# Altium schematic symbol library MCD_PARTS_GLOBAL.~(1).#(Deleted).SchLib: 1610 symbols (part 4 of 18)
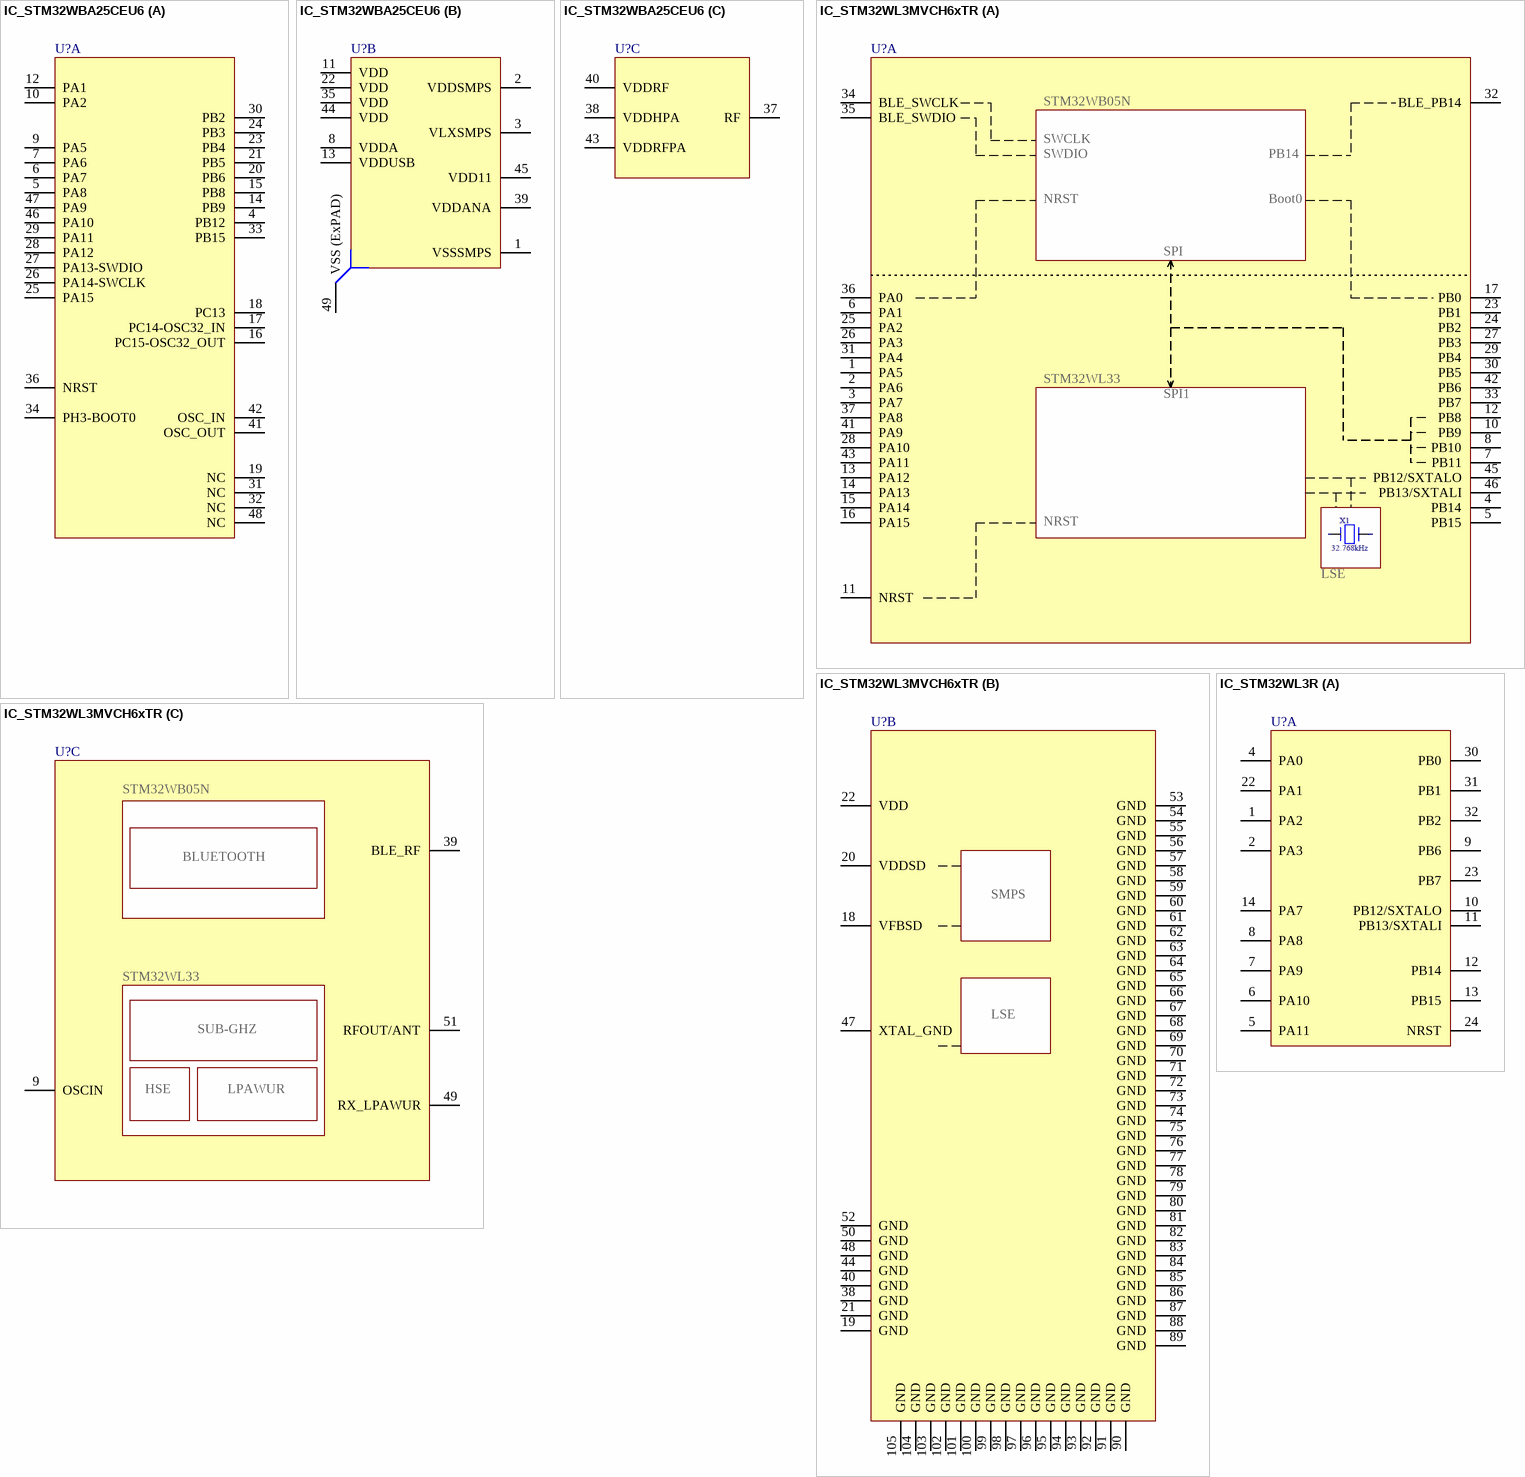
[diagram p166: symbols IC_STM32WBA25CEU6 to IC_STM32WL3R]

## IC_STM32WL3MVCH6xTR
designator U?
part A pins: 1 PA5, 2 PA6, 3 PA7, 4 PB14, 5 PB15, 6 PA1, 7 PB11, 8 PB10, 10 PB9, 11 NRST, 12 PB8, 13 PA12, 14 PA13, 15 PA14, 16 PA15, 17 PB0, 23 PB1, 24 PB2, 25 PA2, 26 PA3, 27 PB3, 28 PA10, 29 PB4, 30 PB5, 31 PA4, 32 BLE_PB14, 33 PB7, 34 BLE_SWCLK, 35 BLE_SWDIO, 36 PA0, 37 PA8, 41 PA9, 42 PB6, 43 PA11, 45 PB12/SXTALO, 46 PB13/SXTALI
part B pins: 18 VFBSD, 19 GND, 20 VDDSD, 21 GND, 22 VDD, 38 GND, 40 GND, 44 GND, 47 XTAL_GND, 48 GND, 50 GND, 52 GND, 53 GND, 54 GND, 55 GND, 56 GND, 57 GND, 58 GND, 59 GND, 60 GND, 61 GND, 62 GND, 63 GND, 64 GND, 65 GND, 66 GND, 67 GND, 68 GND, 69 GND, 70 GND, 71 GND, 72 GND, 73 GND, 74 GND, 75 GND, 76 GND, 77 GND, 78 GND, 79 GND, 80 GND, 81 GND, 82 GND, 83 GND, 84 GND, 85 GND, 86 GND, 87 GND, 88 GND, 89 GND, 90 GND, 91 GND, 92 GND, 93 GND, 94 GND, 95 GND, 96 GND, 97 GND, 98 GND, 99 GND, 100 GND, 101 GND, 102 GND, 103 GND, 104 GND, 105 GND
part C pins: 9 OSCIN, 39 BLE_RF, 49 RX_LPAWUR, 51 RFOUT/ANT

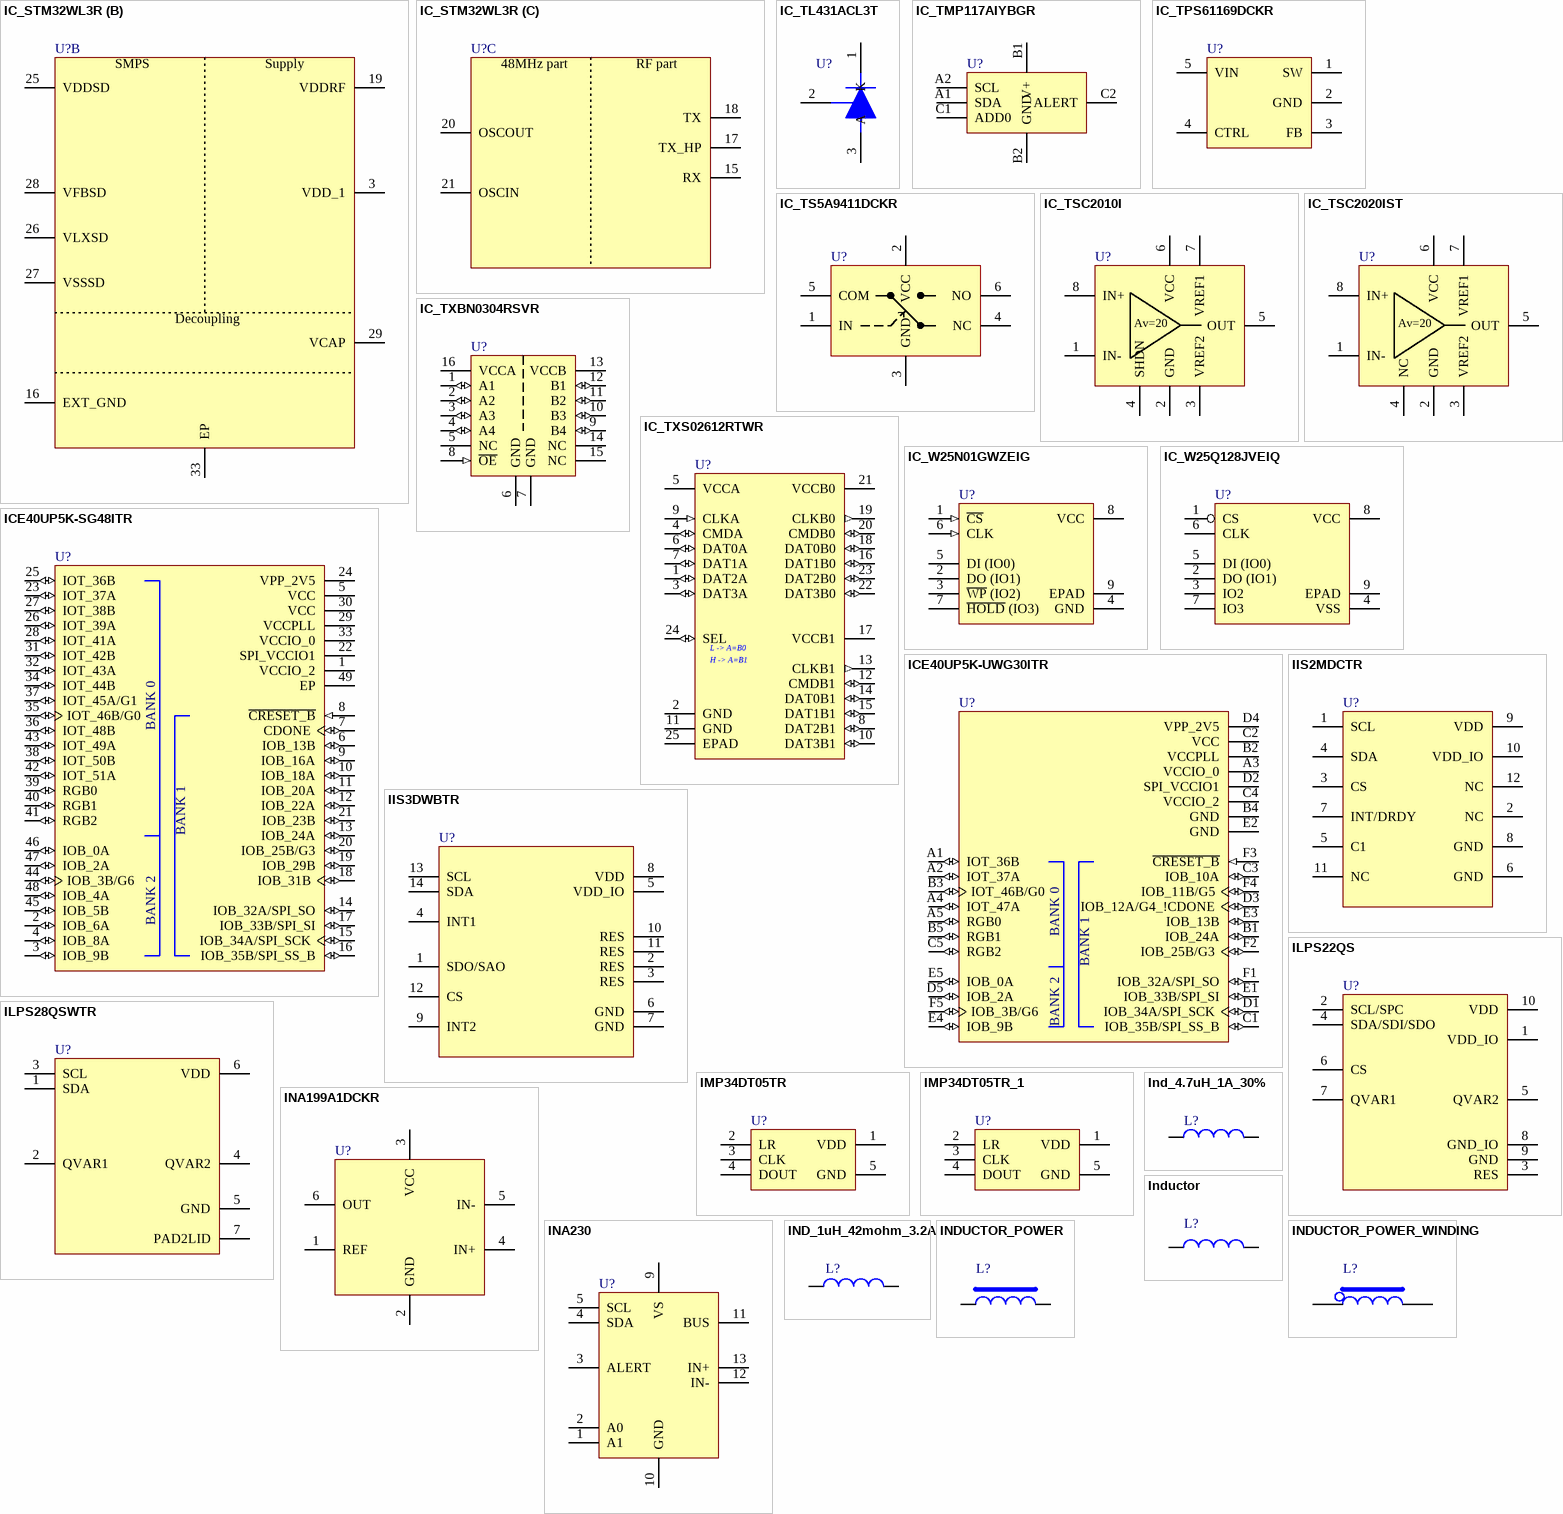
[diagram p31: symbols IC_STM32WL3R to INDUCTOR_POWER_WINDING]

## IC_STM32WL3R
designator U?
part A pins: 1 PA2, 2 PA3, 4 PA0, 5 PA11, 6 PA10, 7 PA9, 8 PA8, 9 PB6, 10 PB12/SXTALO, 11 PB13/SXTALI, 12 PB14, 13 PB15, 14 PA7, 22 PA1, 23 PB7, 24 NRST, 30 PB0, 31 PB1, 32 PB2
part B pins: 3 VDD_1, 16 EXT_GND, 19 VDDRF, 25 VDDSD, 26 VLXSD, 27 VSSSD, 28 VFBSD, 29 VCAP, 33 EP
part C pins: 15 RX, 17 TX_HP, 18 TX, 20 OSCOUT, 21 OSCIN

## IC_TL431ACL3T
designator U?
pins: 1 K, 2 Ref, 3 A

## IC_TMP117AIYBGR
designator U?
pins: A1 SDA, A2 SCL, B1 V+, B2 GND, C1 ADD0, C2 ALERT (oc)

## IC_TPS61169DCKR
designator U?
pins: 1 SW, 2 GND, 3 FB, 4 CTRL, 5 VIN

## IC_TS5A9411DCKR
designator U?
pins: 1 IN, 2 VCC, 3 GND, 4 NC, 5 COM, 6 NO

## IC_TSC2010I
designator U?
An Alternate mode is available
pins: 1 IN-, 2 GND, 3 VREF2, 4 SHDN, 5 OUT, 6 VCC, 7 VREF1, 8 IN+
1 alternate drawing of the same symbol

## IC_TSC2020IST
designator U?
pins: 1 IN-, 2 GND, 3 VREF2, 4 NC, 5 OUT, 6 VCC, 7 VREF1, 8 IN+

## IC_TXBN0304RSVR
designator U?
pins: 1 A1 (io), 2 A2 (io), 3 A3 (io), 4 A4 (io), 5 NC, 6 GND (power), 7 GND (power), 8 ~{OE} (in), 9 B4 (io), 10 B3 (io), 11 B2 (io), 12 B1 (io), 13 VCCB (power), 14 NC, 15 NC, 16 VCCA (power)

## IC_TXS02612RTWR
designator U?
pins: 1 DAT2A (io), 2 GND (power), 3 DAT3A (io), 4 CMDA (io), 5 VCCA (power), 6 DAT0A (io), 7 DAT1A (io), 8 DAT2B1 (io), 9 CLKA (in), 10 DAT3B1 (io), 11 GND (power), 12 CMDB1 (io), 13 CLKB1 (out), 14 DAT0B1 (io), 15 DAT1B1 (io), 16 DAT1B0 (io), 17 VCCB1 (power), 18 DAT0B0 (io), 19 CLKB0 (out), 20 CMDB0 (io), 21 VCCB0 (power), 22 DAT3B0 (io), 23 DAT2B0 (io), 24 SEL (io), 25 EPAD

## IC_W25N01GWZEIG
designator U?
pins: 1 ~{CS} (in), 2 DO (IO1), 3 ~{WP} (IO2), 4 GND, 5 DI (IO0), 6 CLK (in), 7 ~{HOLD} (IO3), 8 VCC, 9 EPAD

## IC_W25Q128JVEIQ
designator U?
pins: 1 CS, 2 DO (IO1), 3 IO2, 4 VSS, 5 DI (IO0), 6 CLK, 7 IO3, 8 VCC, 9 EPAD

## ICE40UP5K-SG48ITR
designator U?
pins: 1 VCCIO_2, 2 IOB_6A (io), 3 IOB_9B (io), 4 IOB_8A (io), 5 VCC, 6 IOB_13B (io), 7 CDONE (io), 8 ~{CRESET_B} (in), 9 IOB_16A (io), 10 IOB_18A (io), 11 IOB_20A (io), 12 IOB_22A (io), 13 IOB_24A (io), 14 IOB_32A/SPI_SO (io), 15 IOB_34A/SPI_SCK (io), 16 IOB_35B/SPI_SS_B (io), 17 IOB_33B/SPI_SI (io), 18 IOB_31B (io), 19 IOB_29B (io), 20 IOB_25B/G3 (io), 21 IOB_23B (io), 22 SPI_VCCIO1, 23 IOT_37A (io), 24 VPP_2V5, 25 IOT_36B (io), 26 IOT_39A (io), 27 IOT_38B (io), 28 IOT_41A (io), 29 VCCPLL, 30 VCC, 31 IOT_42B (io), 32 IOT_43A (io), 33 VCCIO_0, 34 IOT_44B (io), 35 IOT_46B/G0 (io), 36 IOT_48B (io), 37 IOT_45A/G1 (io), 38 IOT_50B (io), 39 RGB0 (io), 40 RGB1 (io), 41 RGB2 (io), 42 IOT_51A (io), 43 IOT_49A (io), 44 IOB_3B/G6 (io), 45 IOB_5B (io), 46 IOB_0A (io), 47 IOB_2A (io), 48 IOB_4A (io), 49 EP

## ICE40UP5K-UWG30ITR
designator U?
pins: A1 IOT_36B (io), A2 IOT_37A (io), A3 VCCIO_0, A4 IOT_47A (io), A5 RGB0 (io), B1 IOB_24A (io), B2 VCCPLL, B3 IOT_46B/G0 (io), B4 GND, B5 RGB1 (io), C1 IOB_35B/SPI_SS_B (io), C2 VCC, C3 IOB_10A (io), C4 VCCIO_2, C5 RGB2 (io), D1 IOB_34A/SPI_SCK (io), D2 SPI_VCCIO1, D3 IOB_12A/G4_!CDONE (io), D4 VPP_2V5, D5 IOB_2A (io), E1 IOB_33B/SPI_SI (io), E2 GND, E3 IOB_13B (io), E4 IOB_9B (io), E5 IOB_0A (io), F1 IOB_32A/SPI_SO (io), F2 IOB_25B/G3 (io), F3 ~{CRESET_B} (in), F4 IOB_11B/G5 (io), F5 IOB_3B/G6 (io)

## IIS2MDCTR
designator U?
pins: 1 SCL, 2 NC, 3 CS, 4 SDA, 5 C1, 6 GND, 7 INT/DRDY, 8 GND, 9 VDD, 10 VDD_IO, 11 NC, 12 NC

## IIS3DWBTR
designator U?
pins: 1 SDO/SAO, 2 RES, 3 RES, 4 INT1, 5 VDD_IO, 6 GND, 7 GND, 8 VDD, 9 INT2, 10 RES, 11 RES, 12 CS, 13 SCL, 14 SDA

## ILPS22QS
designator U?
pins: 1 VDD_IO, 2 SCL/SPC, 3 RES, 4 SDA/SDI/SDO, 5 QVAR2, 6 CS, 7 QVAR1, 8 GND_IO, 9 GND, 10 VDD

## ILPS28QSWTR
designator U?
pins: 1 SDA, 2 QVAR1, 3 SCL, 4 QVAR2, 5 GND, 6 VDD, 7 PAD2LID

## IMP34DT05TR
designator U?
pins: 1 VDD, 2 LR, 3 CLK, 4 DOUT, 5 GND

## IMP34DT05TR_1
designator U?
pins: 1 VDD, 2 LR, 3 CLK, 4 DOUT, 5 GND

## INA199A1DCKR
designator U?
pins: 1 REF, 2 GND, 3 VCC, 4 IN+, 5 IN-, 6 OUT

## INA230
designator U?
pins: 1 A1, 2 A0, 3 ALERT, 4 SDA, 5 SCL, 6 NC hidden, 7 NC hidden, 8 NC hidden, 9 VS, 10 GND, 11 BUS, 12 IN-, 13 IN+, 14 NC hidden, 15 NC hidden, 16 NC hidden

## IND_1uH_42mohm_3.2A
designator L?
pins: 1, 2

## Ind_4.7uH_1A_30%
designator L?
pins: 1, 2

## Inductor
designator L?
An Alternate mode is available
pins: 1, 2
1 alternate drawing of the same symbol

## INDUCTOR_POWER
designator L?
pins: 1, 2

## INDUCTOR_POWER_WINDING
designator L?
pins: 1, 2

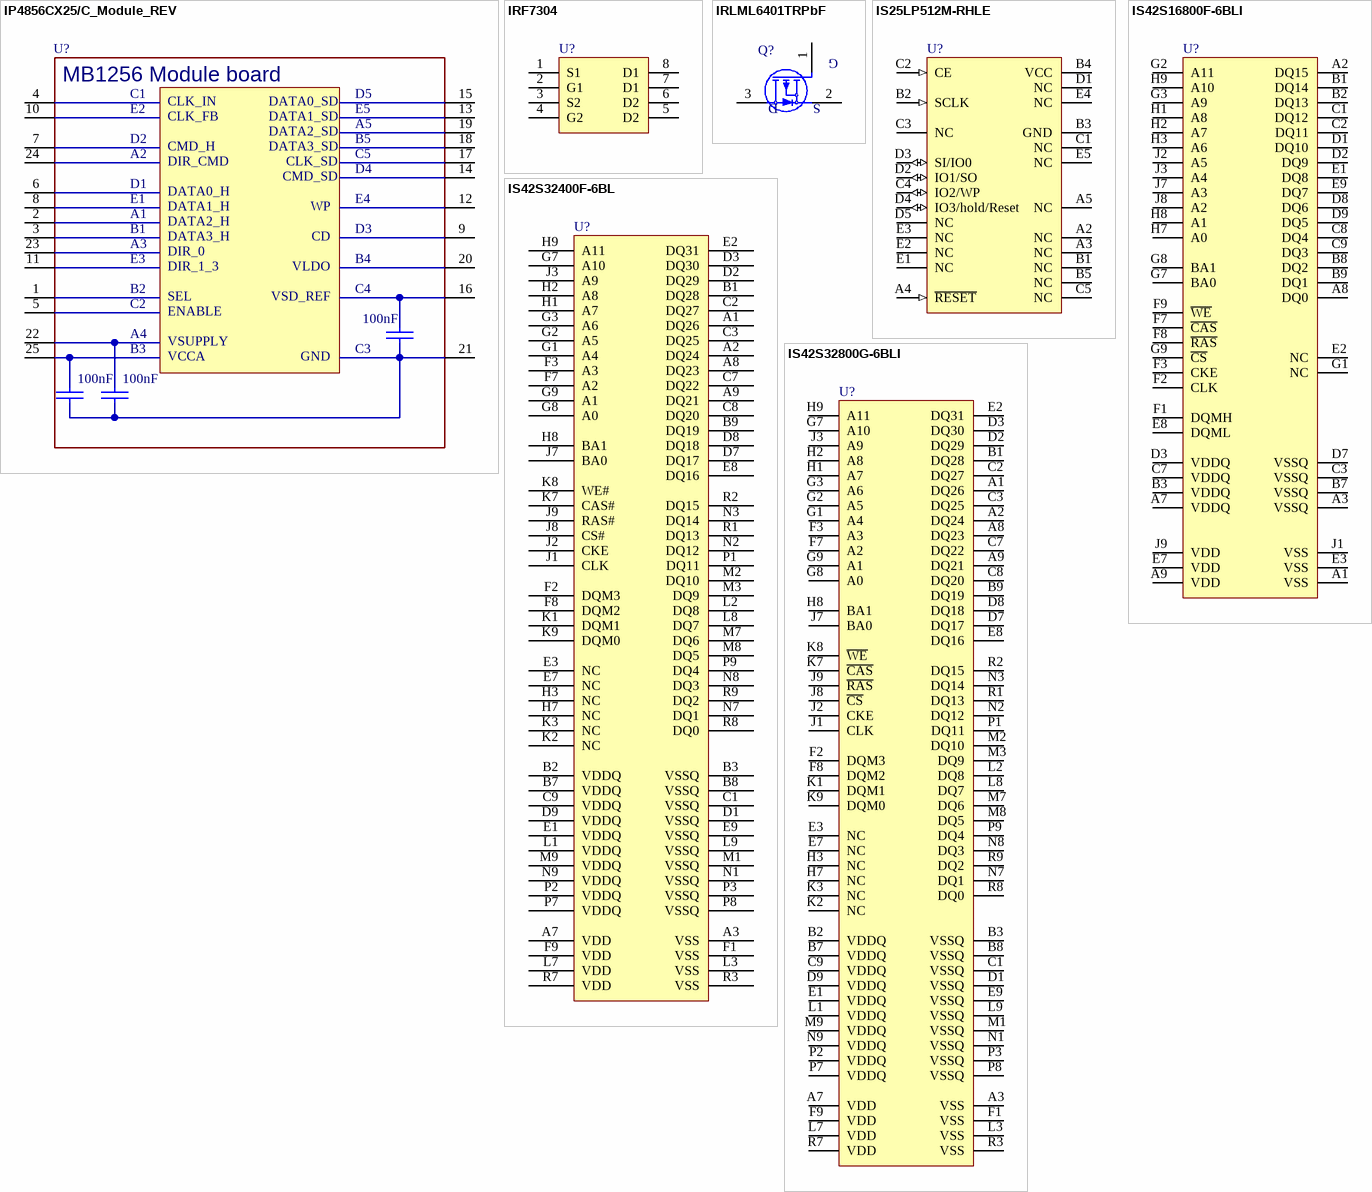
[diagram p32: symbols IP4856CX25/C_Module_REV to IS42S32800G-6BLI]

## IP4856CX25/C_Module_REV
designator U?
pins: 1 CLK_IN, 2 CLK_FB, 3 CMD_H, 4 DIR_CMD, 5 DATA0_H, 6 DATA1_H, 7 DATA2_H, 8 DATA3_H, 9 DIR_0, 10 DIR_1_3, 11 SEL, 12 ENABLE, 13 VSUPPLY, 14 VCCA, 15 DATA0_SD, 16 DATA1_SD, 17 DATA2_SD, 18 DATA3_SD, 19 CLK_SD, 20 CMD_SD, 21 WP, 22 CD, 23 VLDO, 24 VSD_REF, 25 GND

## IRF7304
designator U?
pins: 1 S1, 2 G1, 3 S2, 4 G2, 5 D2, 6 D2, 7 D1, 8 D1

## IRLML6401TRPbF
designator Q?
pins: 1 G, 2 S, 3 D

## IS25LP512M-RHLE
designator U?
pins: A2 NC, A3 NC, A4 ~{RESET} (in), A5 NC, B1 NC, B2 SCLK (in), B3 GND (power), B4 VCC (power), B5 NC, C1 NC (power), C2 CE (in), C3 NC (power), C4 IO2/WP (io), C5 NC, D1 NC (power), D2 IO1/SO (io), D3 SI/IO0 (io), D4 IO3/hold/Reset (io), D5 NC (power), E1 NC (power), E2 NC (power), E3 NC (power), E4 NC (power), E5 NC (power)

## IS42S16800F-6BLI
designator U?
pins: A1 VSS, A2 DQ15, A3 VSSQ, A7 VDDQ, A8 DQ0, A9 VDD, B1 DQ14, B2 DQ13, B3 VDDQ, B7 VSSQ, B8 DQ2, B9 DQ1, C1 DQ12, C2 DQ11, C3 VSSQ, C7 VDDQ, C8 DQ4, C9 DQ3, D1 DQ10, D2 DQ9, D3 VDDQ, D7 VSSQ, D8 DQ6, D9 DQ5, E1 DQ8, E2 NC, E3 VSS, E7 VDD, E8 DQML, E9 DQ7, F1 DQMH, F2 CLK, F3 CKE, F7 ~{CAS}, F8 ~{RAS}, F9 ~{WE}, G1 NC, G2 A11, G3 A9, G7 BA0, G8 BA1, G9 ~{CS}, H1 A8, H2 A7, H3 A6, H7 A0, H8 A1, H9 A10, J1 VSS, J2 A5, J3 A4, J7 A3, J8 A2, J9 VDD

## IS42S32400F-6BL
designator U?
pins: A1 DQ26, A2 DQ24, A3 VSS, A7 VDD, A8 DQ23, A9 DQ21, B1 DQ28, B2 VDDQ, B3 VSSQ, B7 VDDQ, B8 VSSQ, B9 DQ19, C1 VSSQ, C2 DQ27, C3 DQ25, C7 DQ22, C8 DQ20, C9 VDDQ, D1 VSSQ, D2 DQ29, D3 DQ30, D7 DQ17, D8 DQ18, D9 VDDQ, E1 VDDQ, E2 DQ31, E3 NC, E7 NC, E8 DQ16, E9 VSSQ, F1 VSS, F2 DQM3, F3 A3, F7 A2, F8 DQM2, F9 VDD, G1 A4, G2 A5, G3 A6, G7 A10, G8 A0, G9 A1, H1 A7, H2 A8, H3 NC, H7 NC, H8 BA1, H9 A11, J1 CLK, J2 CKE, J3 A9, J7 BA0, J8 CS#, J9 RAS#, K1 DQM1, K2 NC, K3 NC, K7 CAS#, K8 WE#, K9 DQM0, L1 VDDQ, L2 DQ8, L3 VSS, L7 VDD, L8 DQ7, L9 VSSQ, M1 VSSQ, M2 DQ10, M3 DQ9, M7 DQ6, M8 DQ5, M9 VDDQ, N1 VSSQ, N2 DQ12, N3 DQ14, N7 DQ1, N8 DQ3, N9 VDDQ, P1 DQ11, P2 VDDQ, P3 VSSQ, P7 VDDQ, P8 VSSQ, P9 DQ4, R1 DQ13, R2 DQ15, R3 VSS, R7 VDD, R8 DQ0, R9 DQ2

## IS42S32800G-6BLI
designator U?
pins: A1 DQ26, A2 DQ24, A3 VSS, A7 VDD, A8 DQ23, A9 DQ21, B1 DQ28, B2 VDDQ, B3 VSSQ, B7 VDDQ, B8 VSSQ, B9 DQ19, C1 VSSQ, C2 DQ27, C3 DQ25, C7 DQ22, C8 DQ20, C9 VDDQ, D1 VSSQ, D2 DQ29, D3 DQ30, D7 DQ17, D8 DQ18, D9 VDDQ, E1 VDDQ, E2 DQ31, E3 NC, E7 NC, E8 DQ16, E9 VSSQ, F1 VSS, F2 DQM3, F3 A3, F7 A2, F8 DQM2, F9 VDD, G1 A4, G2 A5, G3 A6, G7 A10, G8 A0, G9 A1, H1 A7, H2 A8, H3 NC, H7 NC, H8 BA1, H9 A11, J1 CLK, J2 CKE, J3 A9, J7 BA0, J8 ~{CS}, J9 ~{RAS}, K1 DQM1, K2 NC, K3 NC, K7 ~{CAS}, K8 ~{WE}, K9 DQM0, L1 VDDQ, L2 DQ8, L3 VSS, L7 VDD, L8 DQ7, L9 VSSQ, M1 VSSQ, M2 DQ10, M3 DQ9, M7 DQ6, M8 DQ5, M9 VDDQ, N1 VSSQ, N2 DQ12, N3 DQ14, N7 DQ1, N8 DQ3, N9 VDDQ, P1 DQ11, P2 VDDQ, P3 VSSQ, P7 VDDQ, P8 VSSQ, P9 DQ4, R1 DQ13, R2 DQ15, R3 VSS, R7 VDD, R8 DQ0, R9 DQ2

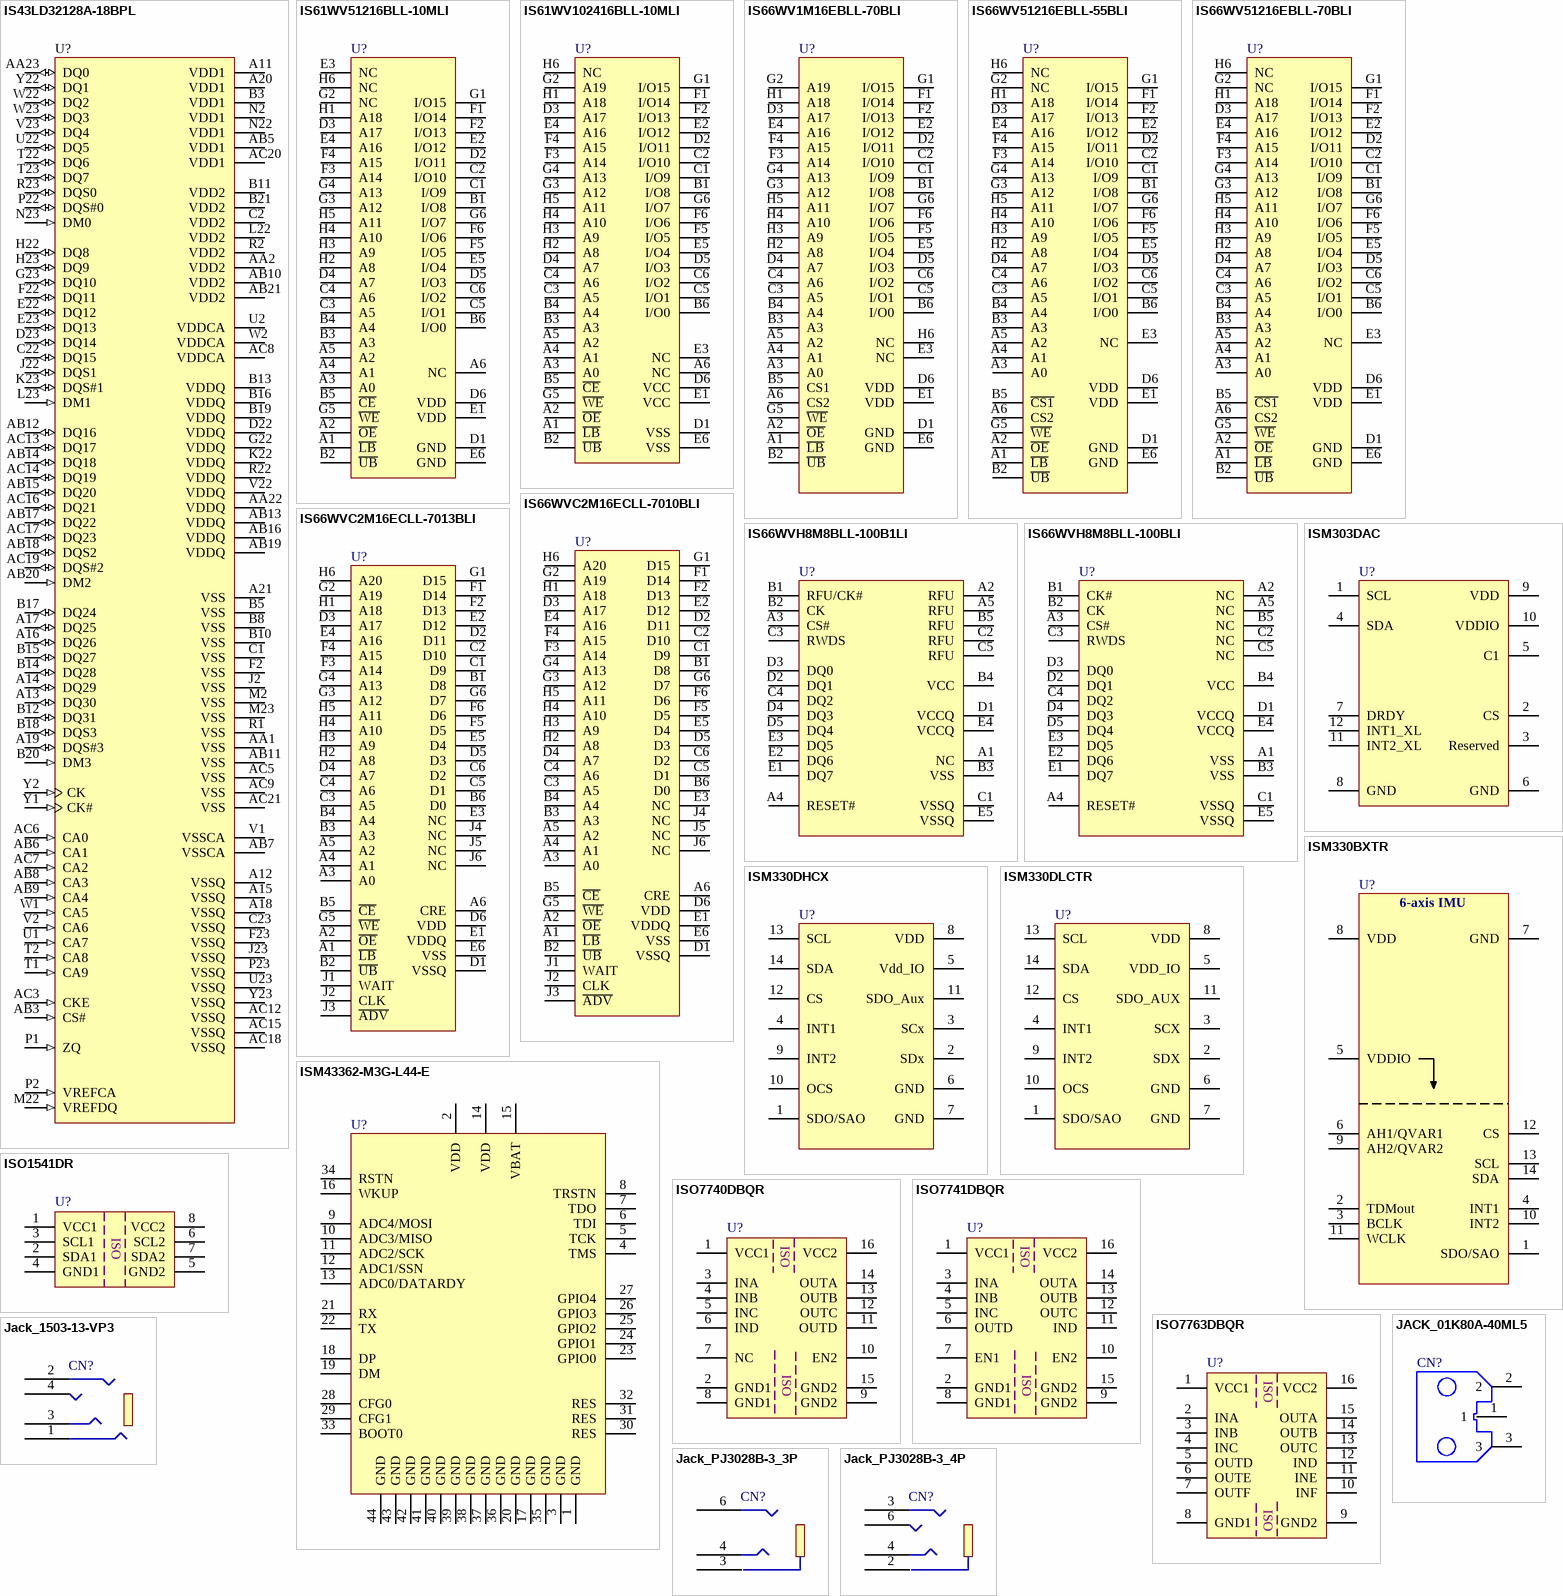
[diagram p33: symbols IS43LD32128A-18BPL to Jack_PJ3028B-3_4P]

## IS43LD32128A-18BPL
designator U?
pins: A11 VDD1 (power) "Core power: Supply 1.", A12 VSSQ (power) "DQ ground: Isolated on the die for improved noise immunity.", A13 DQ30 (io) "Data input/output: Bidirectional data bus.", A14 DQ29 (io) "Data input/output: Bidirectional data bus.", A15 VSSQ (power) "DQ ground: Isolated on the die for improved noise immunity.", A16 DQ26 (io) "Data input/output: Bidirectional data bus.", A17 DQ25 (io) "Data input/output: Bidirectional data bus.", A18 VSSQ (power) "DQ ground: Isolated on the die for improved noise immunity.", A19 DQS#3 (io) "Data strobe: The data strobe is bidirectional (used for read and write data) and complementary (DQS and DQS#). It is edge-aligned output with read data and centered input with write data. DQS[3:0]/DQS[3:0]# is DQS for each (See Datasheet)", A20 VDD1 (power) "Core power: Supply 1.", A21 VSS (power) "Common ground", AA1 VSS (power) "Common ground", AA2 VDD2 (power) "Core power: Supply 2.", AA22 VDDQ (power) "DQ power supply: Isolated on the die for improved noise immunity.", AA23 DQ0 (io) "Data input/output: Bidirectional data bus.", AB3 CS# (in) "Chip select: CS# is considered part of the command code and is sampled at the rising edge of CK.", AB5 VDD1 (power) "Core power: Supply 1.", AB6 CA1 (in) "Command/address inputs: Provide the command and address inputs according to the command truth table.", AB7 VSSCA (power) "Command/address ground: Isolated on the die for improved noise immunity.", AB8 CA3 (in) "Command/address inputs: Provide the command and address inputs according to the command truth table.", AB9 CA4 (in) "Command/address inputs: Provide the command and address inputs according to the command truth table.", AB10 VDD2 (power) "Core power: Supply 2.", AB11 VSS (power) "Common ground", AB12 DQ16 (io) "Data input/output: Bidirectional data bus.", AB13 VDDQ (power) "DQ power supply: Isolated on the die for improved noise immunity.", AB14 DQ18 (io) "Data input/output: Bidirectional data bus.", AB15 DQ20 (io) "Data input/output: Bidirectional data bus.", AB16 VDDQ (power) "DQ power supply: Isolated on the die for improved noise immunity.", AB17 DQ22 (io) "Data input/output: Bidirectional data bus.", AB18 DQS2 (io) "Data strobe: The data strobe is bidirectional (used for read and write data) and complementary (DQS and DQS#). It is edge-aligned output with read data and centered input with write data. DQS[3:0]/DQS[3:0]# is DQS for each (See Datasheet)", AB19 VDDQ (power) "DQ power supply: Isolated on the die for improved noise immunity.", AB20 DM2 (in) "Input data mask: DM is an input mask signal for write data. Although DM balls are input-only, the DM loading is designed to match that of DQ and DQS balls. DM[3:0] is DM for each of the four data bytes, respectively.", AB21 VDD2 (power) "Core power: Supply 2.", AC3 CKE (in) "Clock enable: CKE HIGH activates and CKE LOW deactivates the internal clock signals, input buffers, and output drivers. Power-saving modes are entered and exited via CKE transitions. CKE is considered part of the command (See Datasheet)", AC5 VSS (power) "Common ground", AC6 CA0 (in) "Command/address inputs: Provide the command and address inputs according to the command truth table.", AC7 CA2 (in) "Command/address inputs: Provide the command and address inputs according to the command truth table.", AC8 VDDCA (power) "DQ power supply: Isolated on the die for improved noise immunity.", AC9 VSS (power) "Common ground", AC12 VSSQ (power) "DQ ground: Isolated on the die for improved noise immunity.", AC13 DQ17 (io) "Data input/output: Bidirectional data bus.", AC14 DQ19 (io) "Data input/output: Bidirectional data bus.", AC15 VSSQ (power) "DQ ground: Isolated on the die for improved noise immunity.", AC16 DQ21 (io) "Data input/output: Bidirectional data bus.", AC17 DQ23 (io) "Data input/output: Bidirectional data bus.", AC18 VSSQ (power) "DQ ground: Isolated on the die for improved noise immunity.", AC19 DQS#2 (io) "Data strobe: The data strobe is bidirectional (used for read and write data) and complementary (DQS and DQS#). It is edge-aligned output with read data and centered input with write data. DQS[3:0]/DQS[3:0]# is DQS for each (See Datasheet)", AC20 VDD1 (power) "Core power: Supply 1.", AC21 VSS (power) "Common ground", B3 VDD1 (power) "Core power: Supply 1.", B5 VSS (power) "Common ground", B8 VSS (power) "Common ground", B10 VSS (power) "Common ground", B11 VDD2 (power) "Core power: Supply 2.", B12 DQ31 (io) "Data input/output: Bidirectional data bus.", B13 VDDQ (power) "DQ power supply: Isolated on the die for improved noise immunity.", B14 DQ28 (io) "Data input/output: Bidirectional data bus.", B15 DQ27 (io) "Data input/output: Bidirectional data bus.", B16 VDDQ (power) "DQ power supply: Isolated on the die for improved noise immunity.", B17 DQ24 (io) "Data input/output: Bidirectional data bus.", B18 DQS3 (io) "Data strobe: The data strobe is bidirectional (used for read and write data) and complementary (DQS and DQS#). It is edge-aligned output with read data and centered input with write data. DQS[3:0]/DQS[3:0]# is DQS for each (See Datasheet)", B19 VDDQ (power) "DQ power supply: Isolated on the die for improved noise immunity.", B20 DM3 (in) "Input data mask: DM is an input mask signal for write data. Although DM balls are input-only, the DM loading is designed to match that of DQ and DQS balls. DM[3:0] is DM for each of the four data bytes, respectively.", B21 VDD2 (power) "Core power: Supply 2.", C1 VSS (power) "Common ground", C2 VDD2 (power) "Core power: Supply 2.", C22 DQ15 (io) "Data input/output: Bidirectional data bus.", C23 VSSQ (power) "DQ ground: Isolated on the die for improved noise immunity.", D22 VDDQ (power) "DQ power supply: Isolated on the die for improved noise immunity.", D23 DQ14 (io) "Data input/output: Bidirectional data bus.", E22 DQ12 (io) "Data input/output: Bidirectional data bus.", E23 DQ13 (io) "Data input/output: Bidirectional data bus.", F2 VSS (power) "Common ground", F22 DQ11 (io) "Data input/output: Bidirectional data bus.", F23 VSSQ (power) "DQ ground: Isolated on the die for improved noise immunity.", G22 VDDQ (power) "DQ power supply: Isolated on the die for improved noise immunity.", G23 DQ10 (io) "Data input/output: Bidirectional data bus.", H22 DQ8 (io) "Data input/output: Bidirectional data bus.", H23 DQ9 (io) "Data input/output: Bidirectional data bus.", J2 VSS (power) "Common ground", J22 DQS1 (io) "Data strobe: The data strobe is bidirectional (used for read and write data) and complementary (DQS and DQS#). It is edge-aligned output with read data and centered input with write data. DQS[3:0]/DQS[3:0]# is DQS for each (See Datasheet)", J23 VSSQ (power) "DQ ground: Isolated on the die for improved noise immunity.", K22 VDDQ (power) "DQ power supply: Isolated on the die for improved noise immunity.", K23 DQS#1 (io) "Data strobe: The data strobe is bidirectional (used for read and write data) and complementary (DQS and DQS#). It is edge-aligned output with read data and centered input with write data. DQS[3:0]/DQS[3:0]# is DQS for each (See Datasheet)", L22 VDD2 (power) "Core power: Supply 2.", L23 DM1 (in) "Input data mask: DM is an input mask signal for write data. Although DM balls are input-only, the DM loading is designed to match that of DQ and DQS balls. DM[3:0] is DM for each of the four data bytes, respectively.", M2 VSS (power) "Common ground", M22 VREFDQ (in) "Reference voltage: VREFCA is reference for command/address input buffers, VREFDQ is reference for DQ input buffers.", M23 VSS (power) "Common ground", N2 VDD1 (power) "Core power: Supply 1.", N22 VDD1 (power) "Core power: Supply 1.", N23 DM0 (in) "Input data mask: DM is an input mask signal for write data. Although DM balls are input-only, the DM loading is designed to match that of DQ and DQS balls. DM[3:0] is DM for each of the four data bytes, respectively.", P1 ZQ (in) "External impedance (240 ohm): This signal is used to calibrate the device output impedance for S4 devices. For S2 devices, ZQ should be tied to VDDCA.", P2 VREFCA (in) "Reference voltage: VREFCA is reference for command/address input buffers, VREFDQ is reference for DQ input buffers.", P22 DQS#0 (io) "Data strobe: The data strobe is bidirectional (used for read and write data) and complementary (DQS and DQS#). It is edge-aligned output with read data and centered input with write data. DQS[3:0]/DQS[3:0]# is DQS for each (See Datasheet)", P23 VSSQ (power) "DQ ground: Isolated on the die for improved noise immunity.", R1 VSS (power) "Common ground", R2 VDD2 (power) "Core power: Supply 2.", R22 VDDQ (power) "DQ power supply: Isolated on the die for improved noise immunity.", R23 DQS0 (io) "Data strobe: The data strobe is bidirectional (used for read and write data) and complementary (DQS and DQS#). It is edge-aligned output with read data and centered input with write data. DQS[3:0]/DQS[3:0]# is DQS for each (See Datasheet)", T1 CA9 (in) "Command/address inputs: Provide the command and address inputs according to the command truth table.", T2 CA8 (in) "Command/address inputs: Provide the command and address inputs according to the command truth table.", T22 DQ6 (io) "Data input/output: Bidirectional data bus.", T23 DQ7 (io) "Data input/output: Bidirectional data bus.", U1 CA7 (in) "Command/address inputs: Provide the command and address inputs according to the command truth table.", U2 VDDCA (power) "DQ power supply: Isolated on the die for improved noise immunity.", U22 DQ5 (io) "Data input/output: Bidirectional data bus.", U23 VSSQ (power) "DQ ground: Isolated on the die for improved noise immunity.", V1 VSSCA (power) "Command/address ground: Isolated on the die for improved noise immunity.", V2 CA6 (in) "Command/address inputs: Provide the command and address inputs according to the command truth table.", V22 VDDQ (power) "DQ power supply: Isolated on the die for improved noise immunity.", V23 DQ4 (io) "Data input/output: Bidirectional data bus.", W1 CA5 (in) "Command/address inputs: Provide the command and address inputs according to the command truth table.", W2 VDDCA (power) "DQ power supply: Isolated on the die for improved noise immunity.", W22 DQ2 (io) "Data input/output: Bidirectional data bus.", W23 DQ3 (io) "Data input/output: Bidirectional data bus.", Y1 CK# (in) "Clock: CK and CK# are differential clock inputs. All CA inputs are sampled on both rising and falling edges of CK. CS and CKE inputs are sampled at the rising edge of CK. AC timings are referenced to clock.", Y2 CK (in) "Clock: CK and CK# are differential clock inputs. All CA inputs are sampled on both rising and falling edges of CK. CS and CKE inputs are sampled at the rising edge of CK. AC timings are referenced to clock.", Y22 DQ1 (io) "Data input/output: Bidirectional data bus.", Y23 VSSQ (power) "DQ ground: Isolated on the die for improved noise immunity."

## IS61WV51216BLL-10MLI
designator U?
pins: A1 ~{LB}, A2 ~{OE}, A3 A0, A4 A1, A5 A2, A6 NC, B1 I/O8, B2 ~{UB}, B3 A3, B4 A4, B5 ~{CE}, B6 I/O0, C1 I/O9, C2 I/O10, C3 A5, C4 A6, C5 I/O1, C6 I/O2, D1 GND, D2 I/O11, D3 A17, D4 A7, D5 I/O3, D6 VDD, E1 VDD, E2 I/O12, E3 NC, E4 A16, E5 I/O4, E6 GND, F1 I/O14, F2 I/O13, F3 A14, F4 A15, F5 I/O5, F6 I/O6, G1 I/O15, G2 NC, G3 A12, G4 A13, G5 ~{WE}, G6 I/O7, H1 A18, H2 A8, H3 A9, H4 A10, H5 A11, H6 NC

## IS61WV102416BLL-10MLI
designator U?
pins: A1 ~{LB}, A2 ~{OE}, A3 A0, A4 A1, A5 A2, A6 NC, B1 I/O8, B2 ~{UB}, B3 A3, B4 A4, B5 ~{CE}, B6 I/O0, C1 I/O9, C2 I/O10, C3 A5, C4 A6, C5 I/O1, C6 I/O2, D1 VSS, D2 I/O11, D3 A17, D4 A7, D5 I/O3, D6 VCC, E1 VCC, E2 I/O12, E3 NC, E4 A16, E5 I/O4, E6 VSS, F1 I/O14, F2 I/O13, F3 A14, F4 A15, F5 I/O5, F6 I/O6, G1 I/O15, G2 A19, G3 A12, G4 A13, G5 ~{WE}, G6 I/O7, H1 A18, H2 A8, H3 A9, H4 A10, H5 A11, H6 NC

## IS66WV1M16EBLL-70BLI
designator U?
pins: A1 ~{LB}, A2 ~{OE}, A3 A0, A4 A1, A5 A2, A6 CS2, B1 I/O8, B2 ~{UB}, B3 A3, B4 A4, B5 CS1, B6 I/O0, C1 I/O9, C2 I/O10, C3 A5, C4 A6, C5 I/O1, C6 I/O2, D1 GND, D2 I/O11, D3 A17, D4 A7, D5 I/O3, D6 VDD, E1 VDD, E2 I/O12, E3 NC, E4 A16, E5 I/O4, E6 GND, F1 I/O14, F2 I/O13, F3 A14, F4 A15, F5 I/O5, F6 I/O6, G1 I/O15, G2 A19, G3 A12, G4 A13, G5 ~{WE}, G6 I/O7, H1 A18, H2 A8, H3 A9, H4 A10, H5 A11, H6 NC

## IS66WV51216EBLL-55BLI
designator U?
pins: A1 ~{LB}, A2 ~{OE}, A3 A0, A4 A1, A5 A2, A6 CS2, B1 I/O8, B2 ~{UB}, B3 A3, B4 A4, B5 ~{CS1}, B6 I/O0, C1 I/O9, C2 I/O10, C3 A5, C4 A6, C5 I/O1, C6 I/O2, D1 GND, D2 I/O11, D3 A17, D4 A7, D5 I/O3, D6 VDD, E1 VDD, E2 I/O12, E3 NC, E4 A16, E5 I/O4, E6 GND, F1 I/O14, F2 I/O13, F3 A14, F4 A15, F5 I/O5, F6 I/O6, G1 I/O15, G2 NC, G3 A12, G4 A13, G5 ~{WE}, G6 I/O7, H1 A18, H2 A8, H3 A9, H4 A10, H5 A11, H6 NC

## IS66WV51216EBLL-70BLI
designator U?
pins: A1 ~{LB}, A2 ~{OE}, A3 A0, A4 A1, A5 A2, A6 CS2, B1 I/O8, B2 ~{UB}, B3 A3, B4 A4, B5 ~{CS1}, B6 I/O0, C1 I/O9, C2 I/O10, C3 A5, C4 A6, C5 I/O1, C6 I/O2, D1 GND, D2 I/O11, D3 A17, D4 A7, D5 I/O3, D6 VDD, E1 VDD, E2 I/O12, E3 NC, E4 A16, E5 I/O4, E6 GND, F1 I/O14, F2 I/O13, F3 A14, F4 A15, F5 I/O5, F6 I/O6, G1 I/O15, G2 NC, G3 A12, G4 A13, G5 ~{WE}, G6 I/O7, H1 A18, H2 A8, H3 A9, H4 A10, H5 A11, H6 NC

## IS66WVC2M16ECLL-7010BLI
designator U?
pins: A1 ~{LB}, A2 ~{OE}, A3 A0, A4 A1, A5 A2, A6 CRE, B1 D8, B2 ~{UB}, B3 A3, B4 A4, B5 ~{CE}, B6 D0, C1 D9, C2 D10, C3 A5, C4 A6, C5 D1, C6 D2, D1 VSSQ, D2 D11, D3 A17, D4 A7, D5 D3, D6 VDD, E1 VDDQ, E2 D12, E3 NC, E4 A16, E5 D4, E6 VSS, F1 D14, F2 D13, F3 A14, F4 A15, F5 D5, F6 D6, G1 D15, G2 A19, G3 A12, G4 A13, G5 ~{WE}, G6 D7, H1 A18, H2 A8, H3 A9, H4 A10, H5 A11, H6 A20, J1 WAIT, J2 CLK, J3 ~{ADV}, J4 NC, J5 NC, J6 NC

## IS66WVC2M16ECLL-7013BLI
designator U?
pins: A1 ~{LB}, A2 ~{OE}, A3 A0, A4 A1, A5 A2, A6 CRE, B1 D8, B2 ~{UB}, B3 A3, B4 A4, B5 ~{CE}, B6 D0, C1 D9, C2 D10, C3 A5, C4 A6, C5 D1, C6 D2, D1 VSSQ, D2 D11, D3 A17, D4 A7, D5 D3, D6 VDD, E1 VDDQ, E2 D12, E3 NC, E4 A16, E5 D4, E6 VSS, F1 D14, F2 D13, F3 A14, F4 A15, F5 D5, F6 D6, G1 D15, G2 A19, G3 A12, G4 A13, G5 ~{WE}, G6 D7, H1 A18, H2 A8, H3 A9, H4 A10, H5 A11, H6 A20, J1 WAIT, J2 CLK, J3 ~{ADV}, J4 NC, J5 NC, J6 NC

## IS66WVH8M8BLL-100B1LI
designator U?
pins: A1 NC, A2 RFU, A3 CS#, A4 RESET#, A5 RFU, B1 RFU/CK#, B2 CK, B3 VSS, B4 VCC, B5 RFU, C1 VSSQ, C2 RFU, C3 RWDS, C4 DQ2, C5 RFU, D1 VCCQ, D2 DQ1, D3 DQ0, D4 DQ3, D5 DQ4, E1 DQ7, E2 DQ6, E3 DQ5, E4 VCCQ, E5 VSSQ

## IS66WVH8M8BLL-100BLI
designator U?
pins: A1 VSS, A2 NC, A3 CS#, A4 RESET#, A5 NC, B1 CK#, B2 CK, B3 VSS, B4 VCC, B5 NC, C1 VSSQ, C2 NC, C3 RWDS, C4 DQ2, C5 NC, D1 VCCQ, D2 DQ1, D3 DQ0, D4 DQ3, D5 DQ4, E1 DQ7, E2 DQ6, E3 DQ5, E4 VCCQ, E5 VSSQ

## ISM303DAC
designator U?
pins: 1 SCL, 2 CS, 3 Reserved, 4 SDA, 5 C1, 6 GND, 7 DRDY, 8 GND, 9 VDD, 10 VDDIO, 11 INT2_XL, 12 INT1_XL

## ISM330BXTR
designator U?
pins: 1 SDO/SAO, 2 TDMout, 3 BCLK, 4 INT1, 5 VDDIO, 6 AH1/QVAR1, 7 GND, 8 VDD, 9 AH2/QVAR2, 10 INT2, 11 WCLK, 12 CS, 13 SCL, 14 SDA

## ISM330DHCX
designator U?
pins: 1 SDO/SAO, 2 SDx, 3 SCx, 4 INT1, 5 Vdd_IO, 6 GND, 7 GND, 8 VDD, 9 INT2, 10 OCS, 11 SDO_Aux, 12 CS, 13 SCL, 14 SDA
1 alternate drawing of the same symbol

## ISM330DLCTR
designator U?
pins: 1 SDO/SAO, 2 SDX, 3 SCX, 4 INT1, 5 VDD_IO, 6 GND, 7 GND, 8 VDD, 9 INT2, 10 OCS, 11 SDO_AUX, 12 CS, 13 SCL, 14 SDA

## ISM43362-M3G-L44-E
designator U?
pins: 1 GND, 2 VDD, 3 GND, 4 TMS, 5 TCK, 6 TDI, 7 TDO, 8 TRSTN, 9 ADC4/MOSI, 10 ADC3/MISO, 11 ADC2/SCK, 12 ADC1/SSN, 13 ADC0/DATARDY, 14 VDD, 15 VBAT, 16 WKUP, 17 GND, 18 DP, 19 DM, 20 GND, 21 RX, 22 TX, 23 GPIO0, 24 GPIO1, 25 GPIO2, 26 GPIO3, 27 GPIO4, 28 CFG0, 29 CFG1, 30 RES, 31 RES, 32 RES, 33 BOOT0, 34 RSTN, 35 GND, 36 GND, 37 GND, 38 GND, 39 GND, 40 GND, 41 GND, 42 GND, 43 GND, 44 GND

## ISO1541DR
designator U?
pins: 1 VCC1 (power), 2 SDA1, 3 SCL1 (power), 4 GND1 (power), 5 GND2 (power), 6 SCL2, 7 SDA2, 8 VCC2 (power)

## ISO7740DBQR
designator U?
pins: 1 VCC1 (power), 2 GND1 (power), 3 INA, 4 INB, 5 INC, 6 IND, 7 NC, 8 GND1 (power), 9 GND2 (power), 10 EN2, 11 OUTD, 12 OUTC, 13 OUTB, 14 OUTA, 15 GND2 (power), 16 VCC2 (power)

## ISO7741DBQR
designator U?
pins: 1 VCC1 (power), 2 GND1 (power), 3 INA, 4 INB, 5 INC, 6 OUTD, 7 EN1, 8 GND1 (power), 9 GND2 (power), 10 EN2, 11 IND, 12 OUTC, 13 OUTB, 14 OUTA, 15 GND2 (power), 16 VCC2 (power)

## ISO7763DBQR
designator U?
pins: 1 VCC1 (power), 2 INA, 3 INB, 4 INC, 5 OUTD, 6 OUTE, 7 OUTF, 8 GND1 (power), 9 GND2 (power), 10 INF, 11 INE, 12 IND, 13 OUTC, 14 OUTB, 15 OUTA, 16 VCC2 (power)

## JACK_01K80A-40ML5
designator CN?
pins: 1, 2, 3

## Jack_1503-13-VP3
designator CN?
pins: 1, 2, 3, 4

## Jack_PJ3028B-3_3P
designator CN?
pins: 3, 4, 6

## Jack_PJ3028B-3_4P
designator CN?
pins: 2, 3, 4, 6

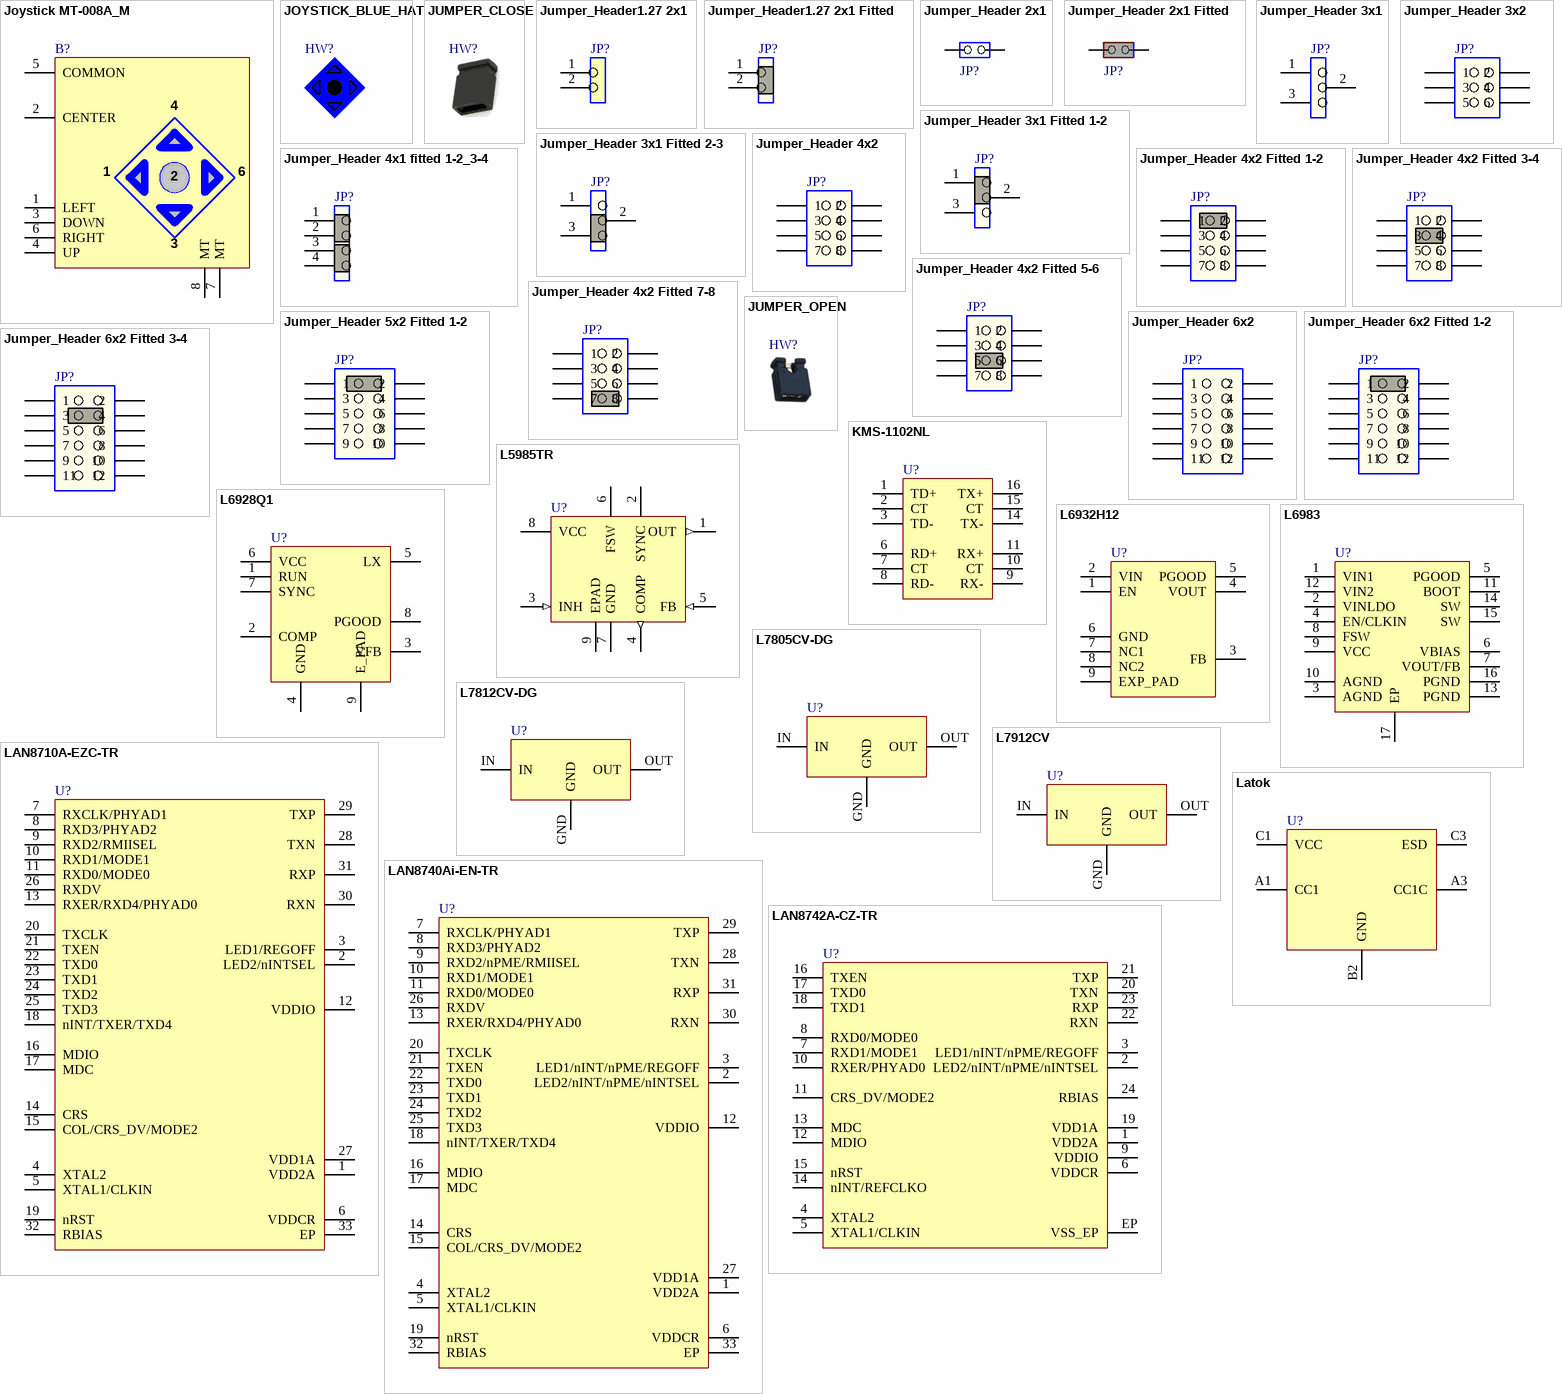
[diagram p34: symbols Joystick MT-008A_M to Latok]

## Joystick MT-008A_M
designator B?
pins: 1 LEFT, 2 CENTER, 3 DOWN, 4 UP, 5 COMMON, 6 RIGHT, 7 MT, 8 MT

## JOYSTICK_BLUE_HAT
designator HW?  (mechanical)

## JUMPER_CLOSE
designator HW?

## Jumper_Header1.27 2x1
designator JP?
pins: 1, 2

## Jumper_Header1.27 2x1 Fitted
designator JP?
pins: 1, 2

## Jumper_Header 2x1
designator JP?
pins: 1 COMMON, 2 NO

## Jumper_Header 2x1 Fitted
designator JP?
pins: 1 COMMON, 2 NO

## Jumper_Header 3x1
designator JP?
pins: 1, 2, 3

## Jumper_Header 3x1 Fitted 1-2
designator JP?
pins: 1, 2, 3

## Jumper_Header 3x1 Fitted 2-3
designator JP?
pins: 1, 2, 3

## Jumper_Header 3x2
designator JP?
pins: 1, 2, 3, 4, 5, 6

## Jumper_Header 4x1 fitted 1-2_3-4
designator JP?
pins: 1, 2, 3, 4

## Jumper_Header 4x2
designator JP?
pins: 1, 2, 3, 4, 5, 6, 7, 8

## Jumper_Header 4x2 Fitted 1-2
designator JP?
pins: 1, 2, 3, 4, 5, 6, 7, 8

## Jumper_Header 4x2 Fitted 3-4
designator JP?
pins: 1, 2, 3, 4, 5, 6, 7, 8

## Jumper_Header 4x2 Fitted 5-6
designator JP?
pins: 1, 2, 3, 4, 5, 6, 7, 8

## Jumper_Header 4x2 Fitted 7-8
designator JP?
pins: 1, 2, 3, 4, 5, 6, 7, 8

## Jumper_Header 5x2 Fitted 1-2
designator JP?
pins: 1, 2, 3, 4, 5, 6, 7, 8, 9, 10

## Jumper_Header 6x2
designator JP?
pins: 1, 2, 3, 4, 5, 6, 7, 8, 9, 10, 11, 12

## Jumper_Header 6x2 Fitted 1-2
designator JP?
pins: 1, 2, 3, 4, 5, 6, 7, 8, 9, 10, 11, 12

## Jumper_Header 6x2 Fitted 3-4
designator JP?
pins: 1, 2, 3, 4, 5, 6, 7, 8, 9, 10, 11, 12

## JUMPER_OPEN
designator HW?

## KMS-1102NL
designator U?
pins: 1 TD+, 2 CT, 3 TD-, 6 RD+, 7 CT, 8 RD-, 9 RX-, 10 CT, 11 RX+, 14 TX-, 15 CT, 16 TX+
1 alternate drawing of the same symbol

## L5985TR
designator U?
pins: 1 OUT (out), 2 SYNC, 3 INH (in), 4 COMP (out), 5 FB (in), 6 FSW, 7 GND, 8 VCC (power), 9 EPAD

## L6928Q1
designator U?
pins: 1 RUN, 2 COMP, 3 VFB, 4 GND, 5 LX, 6 VCC, 7 SYNC, 8 PGOOD, 9 E_PAD

## L6932H12
designator U?
pins: 1 EN, 2 VIN, 3 FB, 4 VOUT, 5 PGOOD, 6 GND, 7 NC1, 8 NC2, 9 EXP_PAD

## L6983
designator U?
pins: 1 VIN1, 2 VINLDO, 3 AGND, 4 EN/CLKIN, 5 PGOOD, 6 VBIAS, 7 VOUT/FB, 8 FSW, 9 VCC, 10 AGND, 11 BOOT, 12 VIN2, 13 PGND, 14 SW, 15 SW, 16 PGND, 17 EP

## L7805CV-DG
designator U?
pins: GND (power), IN (power), OUT (power)

## L7812CV-DG
designator U?
pins: GND (power), IN (power), OUT (power)

## L7912CV
designator U?
pins: GND (power), IN (power), OUT (power)

## LAN8710A-EZC-TR
designator U?
pins: 1 VDD2A, 2 LED2/nINTSEL, 3 LED1/REGOFF, 4 XTAL2, 5 XTAL1/CLKIN, 6 VDDCR, 7 RXCLK/PHYAD1, 8 RXD3/PHYAD2, 9 RXD2/RMIISEL, 10 RXD1/MODE1, 11 RXD0/MODE0, 12 VDDIO, 13 RXER/RXD4/PHYAD0, 14 CRS, 15 COL/CRS_DV/MODE2, 16 MDIO, 17 MDC, 18 nINT/TXER/TXD4, 19 nRST, 20 TXCLK, 21 TXEN, 22 TXD0, 23 TXD1, 24 TXD2, 25 TXD3, 26 RXDV, 27 VDD1A, 28 TXN, 29 TXP, 30 RXN, 31 RXP, 32 RBIAS, 33 EP

## LAN8740Ai-EN-TR
designator U?
pins: 1 VDD2A, 2 LED2/nINT/nPME/nINTSEL, 3 LED1/nINT/nPME/REGOFF, 4 XTAL2, 5 XTAL1/CLKIN, 6 VDDCR, 7 RXCLK/PHYAD1, 8 RXD3/PHYAD2, 9 RXD2/nPME/RMIISEL, 10 RXD1/MODE1, 11 RXD0/MODE0, 12 VDDIO, 13 RXER/RXD4/PHYAD0, 14 CRS, 15 COL/CRS_DV/MODE2, 16 MDIO, 17 MDC, 18 nINT/TXER/TXD4, 19 nRST, 20 TXCLK, 21 TXEN, 22 TXD0, 23 TXD1, 24 TXD2, 25 TXD3, 26 RXDV, 27 VDD1A, 28 TXN, 29 TXP, 30 RXN, 31 RXP, 32 RBIAS, 33 EP

## LAN8742A-CZ-TR
designator U?
pins: 1 VDD2A, 2 LED2/nINT/nPME/nINTSEL, 3 LED1/nINT/nPME/REGOFF, 4 XTAL2, 5 XTAL1/CLKIN, 6 VDDCR, 7 RXD1/MODE1, 8 RXD0/MODE0, 9 VDDIO, 10 RXER/PHYAD0, 11 CRS_DV/MODE2, 12 MDIO, 13 MDC, 14 nINT/REFCLKO, 15 nRST, 16 TXEN, 17 TXD0, 18 TXD1, 19 VDD1A, 20 TXN, 21 TXP, 22 RXN, 23 RXP, 24 RBIAS, EP VSS_EP
1 alternate drawing of the same symbol

## Latok
designator U?
pins: A1 CC1, A3 CC1C, B2 GND, C1 VCC (power), C3 ESD

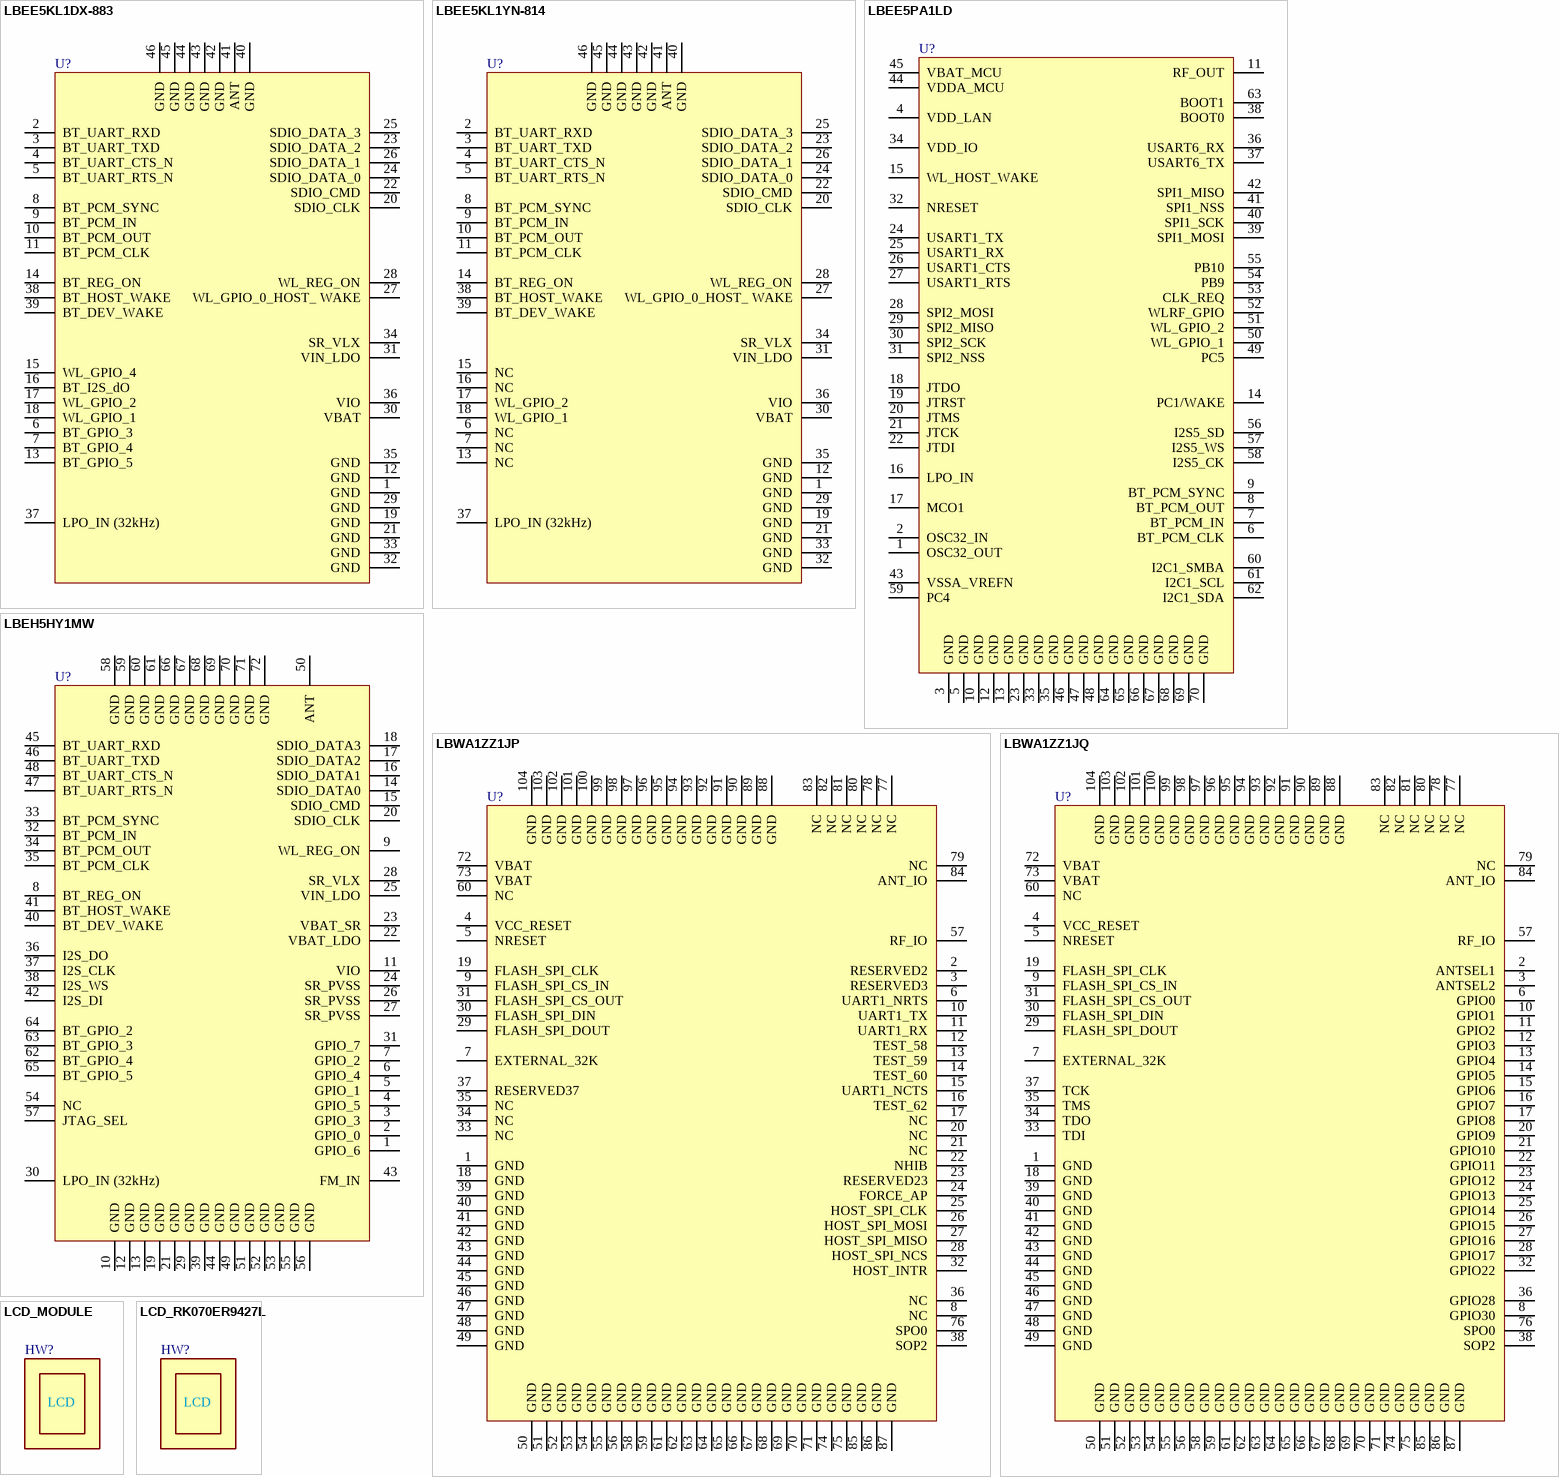
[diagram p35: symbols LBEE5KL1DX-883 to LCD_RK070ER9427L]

## LBEE5KL1DX-883
designator U?
pins: 1 GND, 2 BT_UART_RXD, 3 BT_UART_TXD, 4 BT_UART_CTS_N, 5 BT_UART_RTS_N, 6 BT_GPIO_3, 7 BT_GPIO_4, 8 BT_PCM_SYNC, 9 BT_PCM_IN, 10 BT_PCM_OUT, 11 BT_PCM_CLK, 12 GND, 13 BT_GPIO_5, 14 BT_REG_ON, 15 WL_GPIO_4, 16 BT_I2S_dO, 17 WL_GPIO_2, 18 WL_GPIO_1, 19 GND, 20 SDIO_CLK, 21 GND, 22 SDIO_CMD, 23 SDIO_DATA_2, 24 SDIO_DATA_0, 25 SDIO_DATA_3, 26 SDIO_DATA_1, 27 WL_GPIO_0_HOST_ WAKE, 28 WL_REG_ON, 29 GND, 30 VBAT, 31 VIN_LDO, 32 GND, 33 GND, 34 SR_VLX, 35 GND, 36 VIO, 37 LPO_IN (32kHz), 38 BT_HOST_WAKE, 39 BT_DEV_WAKE, 40 GND, 41 ANT, 42 GND, 43 GND, 44 GND, 45 GND, 46 GND

## LBEE5KL1YN-814
designator U?
pins: 1 GND, 2 BT_UART_RXD, 3 BT_UART_TXD, 4 BT_UART_CTS_N, 5 BT_UART_RTS_N, 6 NC, 7 NC, 8 BT_PCM_SYNC, 9 BT_PCM_IN, 10 BT_PCM_OUT, 11 BT_PCM_CLK, 12 GND, 13 NC, 14 BT_REG_ON, 15 NC, 16 NC, 17 WL_GPIO_2, 18 WL_GPIO_1, 19 GND, 20 SDIO_CLK, 21 GND, 22 SDIO_CMD, 23 SDIO_DATA_2, 24 SDIO_DATA_0, 25 SDIO_DATA_3, 26 SDIO_DATA_1, 27 WL_GPIO_0_HOST_ WAKE, 28 WL_REG_ON, 29 GND, 30 VBAT, 31 VIN_LDO, 32 GND, 33 GND, 34 SR_VLX, 35 GND, 36 VIO, 37 LPO_IN (32kHz), 38 BT_HOST_WAKE, 39 BT_DEV_WAKE, 40 GND, 41 ANT, 42 GND, 43 GND, 44 GND, 45 GND, 46 GND

## LBEE5PA1LD
designator U?
pins: 1 OSC32_OUT, 2 OSC32_IN, 3 GND, 4 VDD_LAN, 5 GND, 6 BT_PCM_CLK, 7 BT_PCM_IN, 8 BT_PCM_OUT, 9 BT_PCM_SYNC, 10 GND, 11 RF_OUT, 12 GND, 13 GND, 14 PC1/WAKE, 15 WL_HOST_WAKE, 16 LPO_IN, 17 MCO1, 18 JTDO, 19 JTRST, 20 JTMS, 21 JTCK, 22 JTDI, 23 GND, 24 USART1_TX, 25 USART1_RX, 26 USART1_CTS, 27 USART1_RTS, 28 SPI2_MOSI, 29 SPI2_MISO, 30 SPI2_SCK, 31 SPI2_NSS, 32 NRESET, 33 GND, 34 VDD_IO, 35 GND, 36 USART6_RX, 37 USART6_TX, 38 BOOT0, 39 SPI1_MOSI, 40 SPI1_SCK, 41 SPI1_NSS, 42 SPI1_MISO, 43 VSSA_VREFN, 44 VDDA_MCU, 45 VBAT_MCU, 46 GND, 47 GND, 48 GND, 49 PC5, 50 WL_GPIO_1, 51 WL_GPIO_2, 52 WLRF_GPIO, 53 CLK_REQ, 54 PB9, 55 PB10, 56 I2S5_SD, 57 I2S5_WS, 58 I2S5_CK, 59 PC4, 60 I2C1_SMBA, 61 I2C1_SCL, 62 I2C1_SDA, 63 BOOT1, 64 GND, 65 GND, 66 GND, 67 GND, 68 GND, 69 GND, 70 GND

## LBEH5HY1MW
designator U?
pins: 1 GPIO_6, 2 GPIO_0, 3 GPIO_3, 4 GPIO_5, 5 GPIO_1, 6 GPIO_4, 7 GPIO_2, 8 BT_REG_ON, 9 WL_REG_ON, 10 GND, 11 VIO, 12 GND, 13 GND, 14 SDIO_DATA0, 15 SDIO_CMD, 16 SDIO_DATA1, 17 SDIO_DATA2, 18 SDIO_DATA3, 19 GND, 20 SDIO_CLK, 21 GND, 22 VBAT_LDO, 23 VBAT_SR, 24 SR_PVSS, 25 VIN_LDO, 26 SR_PVSS, 27 SR_PVSS, 28 SR_VLX, 29 GND, 30 LPO_IN (32kHz), 31 GPIO_7, 32 BT_PCM_IN, 33 BT_PCM_SYNC, 34 BT_PCM_OUT, 35 BT_PCM_CLK, 36 I2S_DO, 37 I2S_CLK, 38 I2S_WS, 39 GND, 40 BT_DEV_WAKE, 41 BT_HOST_WAKE, 42 I2S_DI, 43 FM_IN, 44 GND, 45 BT_UART_RXD, 46 BT_UART_TXD, 47 BT_UART_RTS_N, 48 BT_UART_CTS_N, 49 GND, 50 ANT, 51 GND, 52 GND, 53 GND, 54 NC, 55 GND, 56 GND, 57 JTAG_SEL, 58 GND, 59 GND, 60 GND, 61 GND, 62 BT_GPIO_4, 63 BT_GPIO_3, 64 BT_GPIO_2, 65 BT_GPIO_5, 66 GND, 67 GND, 68 GND, 69 GND, 70 GND, 71 GND, 72 GND

## LBWA1ZZ1JP
designator U?
pins: 1 GND, 2 RESERVED2, 3 RESERVED3, 4 VCC_RESET, 5 NRESET, 6 UART1_NRTS, 7 EXTERNAL_32K, 8 NC, 9 FLASH_SPI_CS_IN, 10 UART1_TX, 11 UART1_RX, 12 TEST_58, 13 TEST_59, 14 TEST_60, 15 UART1_NCTS, 16 TEST_62, 17 NC, 18 GND, 19 FLASH_SPI_CLK, 20 NC, 21 NC, 22 NHIB, 23 RESERVED23, 24 FORCE_AP, 25 HOST_SPI_CLK, 26 HOST_SPI_MOSI, 27 HOST_SPI_MISO, 28 HOST_SPI_NCS, 29 FLASH_SPI_DOUT, 30 FLASH_SPI_DIN, 31 FLASH_SPI_CS_OUT, 32 HOST_INTR, 33 NC, 34 NC, 35 NC, 36 NC, 37 RESERVED37, 38 SOP2, 39 GND, 40 GND, 41 GND, 42 GND, 43 GND, 44 GND, 45 GND, 46 GND, 47 GND, 48 GND, 49 GND, 50 GND, 51 GND, 52 GND, 53 GND, 54 GND, 55 GND, 56 GND, 57 RF_IO, 58 GND, 59 GND, 60 NC, 61 GND, 62 GND, 63 GND, 64 GND, 65 GND, 66 GND, 67 GND, 68 GND, 69 GND, 70 GND, 71 GND, 72 VBAT, 73 VBAT, 74 GND, 75 GND, 76 SPO0, 77 NC, 78 NC, 79 NC, 80 NC, 81 NC, 82 NC, 83 NC, 84 ANT_IO, 85 GND, 86 GND, 87 GND, 88 GND, 89 GND, 90 GND, 91 GND, 92 GND, 93 GND, 94 GND, 95 GND, 96 GND, 97 GND, 98 GND, 99 GND, 100 GND, 101 GND, 102 GND, 103 GND, 104 GND

## LBWA1ZZ1JQ
designator U?
pins: 1 GND, 2 ANTSEL1, 3 ANTSEL2, 4 VCC_RESET, 5 NRESET, 6 GPIO0, 7 EXTERNAL_32K, 8 GPIO30, 9 FLASH_SPI_CS_IN, 10 GPIO1, 11 GPIO2, 12 GPIO3, 13 GPIO4, 14 GPIO5, 15 GPIO6, 16 GPIO7, 17 GPIO8, 18 GND, 19 FLASH_SPI_CLK, 20 GPIO9, 21 GPIO10, 22 GPIO11, 23 GPIO12, 24 GPIO13, 25 GPIO14, 26 GPIO15, 27 GPIO16, 28 GPIO17, 29 FLASH_SPI_DOUT, 30 FLASH_SPI_DIN, 31 FLASH_SPI_CS_OUT, 32 GPIO22, 33 TDI, 34 TDO, 35 TMS, 36 GPIO28, 37 TCK, 38 SOP2, 39 GND, 40 GND, 41 GND, 42 GND, 43 GND, 44 GND, 45 GND, 46 GND, 47 GND, 48 GND, 49 GND, 50 GND, 51 GND, 52 GND, 53 GND, 54 GND, 55 GND, 56 GND, 57 RF_IO, 58 GND, 59 GND, 60 NC, 61 GND, 62 GND, 63 GND, 64 GND, 65 GND, 66 GND, 67 GND, 68 GND, 69 GND, 70 GND, 71 GND, 72 VBAT, 73 VBAT, 74 GND, 75 GND, 76 SPO0, 77 NC, 78 NC, 79 NC, 80 NC, 81 NC, 82 NC, 83 NC, 84 ANT_IO, 85 GND, 86 GND, 87 GND, 88 GND, 89 GND, 90 GND, 91 GND, 92 GND, 93 GND, 94 GND, 95 GND, 96 GND, 97 GND, 98 GND, 99 GND, 100 GND, 101 GND, 102 GND, 103 GND, 104 GND

## LCD_MODULE
designator HW?  (mechanical)

## LCD_RK070ER9427L
designator HW?

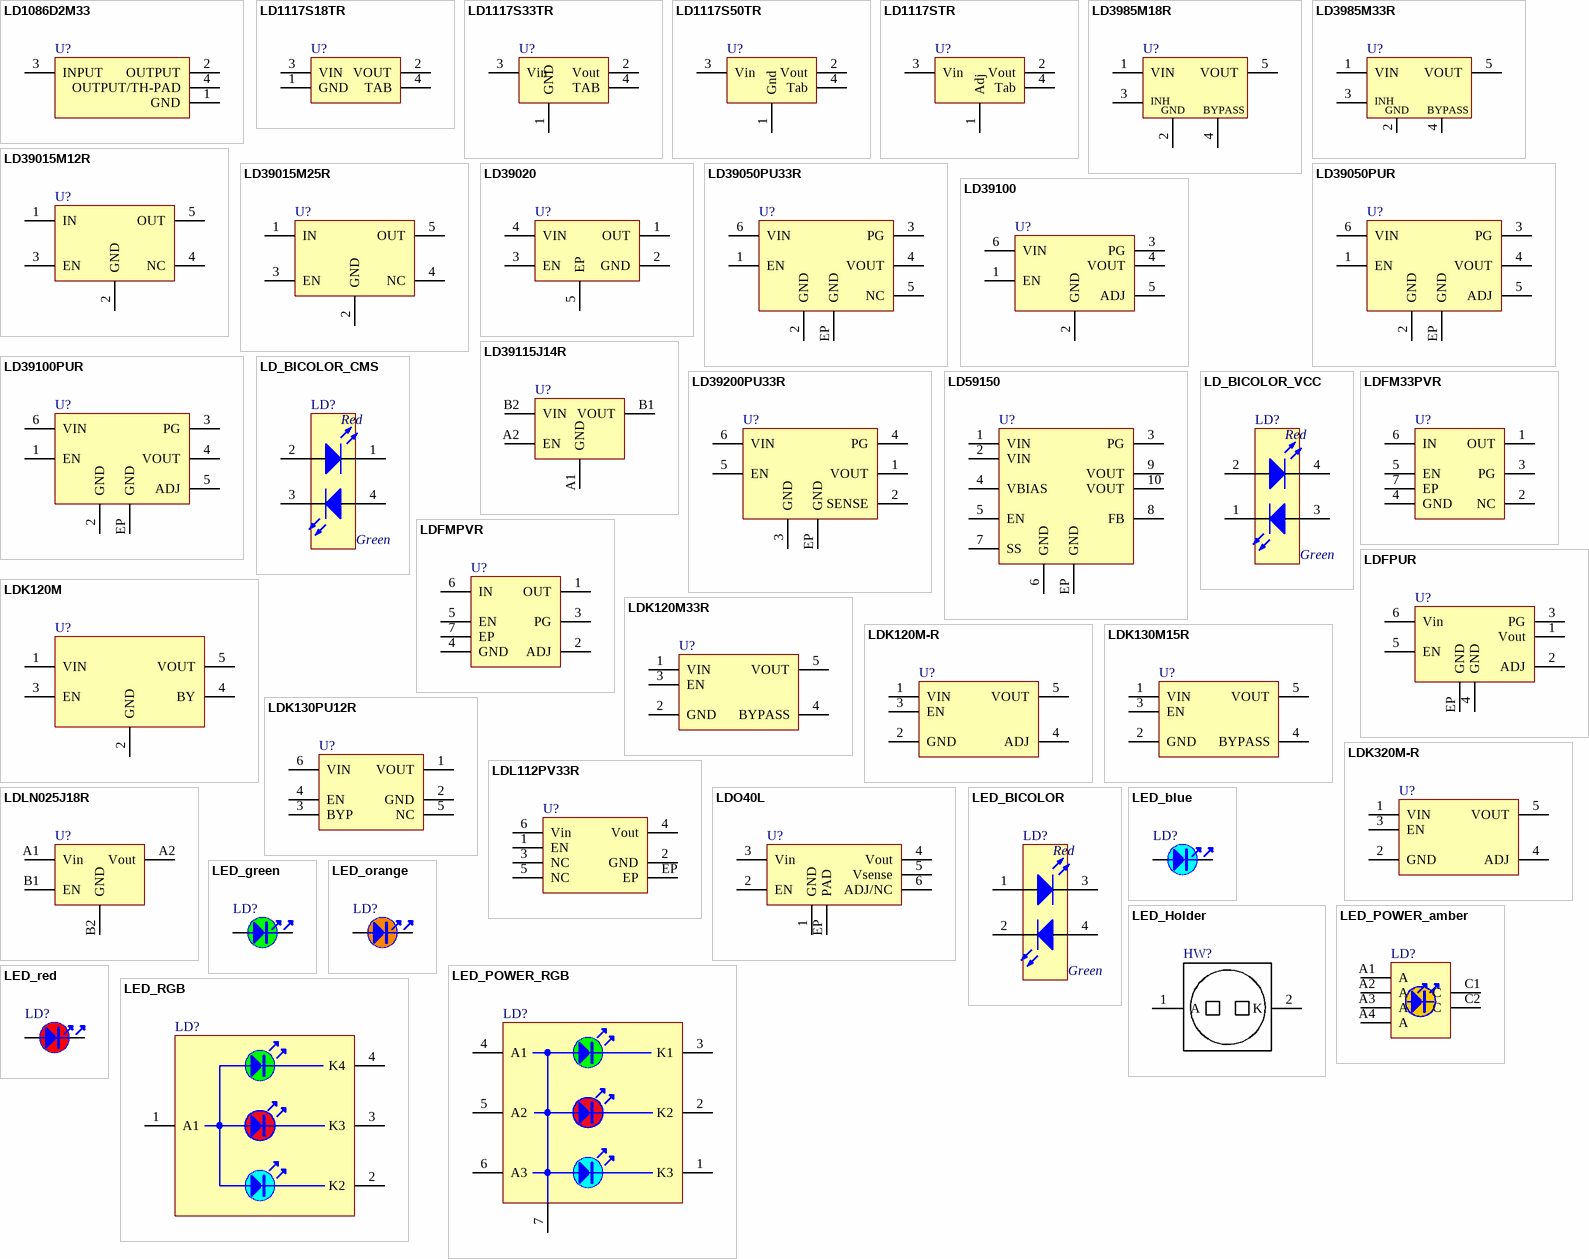
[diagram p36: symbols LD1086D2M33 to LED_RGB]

## LD1086D2M33
designator U?
pins: 1 GND, 2 OUTPUT, 3 INPUT, 4 OUTPUT/TH-PAD

## LD1117S18TR
designator U?
pins: 1 GND (power), 2 VOUT (power), 3 VIN (power), 4 TAB (power)

## LD1117S33TR
designator U?
pins: 1 GND, 2 Vout, 3 Vin, 4 TAB

## LD1117S50TR
designator U?
pins: 1 Gnd, 2 Vout, 3 Vin, 4 Tab

## LD1117STR
designator U?
pins: 1 Adj, 2 Vout, 3 Vin, 4 Tab

## LD3985M18R
designator U?
pins: 1 VIN, 2 GND, 3 CE, 4 BYPASS, 5 VOUT

## LD3985M33R
designator U?
pins: 1 VIN, 2 GND, 3 CE, 4 BYPASS, 5 VOUT

## LD39015M12R
designator U?
pins: 1 IN, 2 GND, 3 EN, 4 NC, 5 OUT

## LD39015M25R
designator U?
pins: 1 IN, 2 GND, 3 EN, 4 NC, 5 OUT

## LD39020
designator U?
pins: 1 OUT, 2 GND, 3 EN, 4 VIN, 5 EP

## LD39050PU33R
designator U?
pins: 1 EN, 2 GND, 3 PG, 4 VOUT, 5 NC, 6 VIN, EP GND

## LD39050PUR
designator U?
pins: 1 EN, 2 GND, 3 PG, 4 VOUT, 5 ADJ, 6 VIN, EP GND

## LD39100
designator U?
pins: 1 EN, 2 GND, 3 PG, 4 VOUT, 5 ADJ, 6 VIN

## LD39100PUR
designator U?
pins: 1 EN, 2 GND, 3 PG, 4 VOUT, 5 ADJ, 6 VIN, EP GND

## LD39115J14R
designator U?
pins: A1 GND, A2 EN, B1 VOUT, B2 VIN

## LD39200PU33R
designator U?
pins: 1 VOUT, 2 SENSE, 3 GND, 4 PG, 5 EN, 6 VIN, EP GND
1 alternate drawing of the same symbol

## LD59150
designator U?
pins: 1 VIN, 2 VIN, 3 PG, 4 VBIAS, 5 EN, 6 GND, 7 SS, 8 FB, 9 VOUT, 10 VOUT, EP GND

## LD_BICOLOR_CMS
designator LD?
pins: 1 RED_cathode, 2 Red_anode, 3 YellowGreen_cathode, 4 YellowGreen_anode

## LD_BICOLOR_VCC
designator LD?
pins: 1 YellowGreen_cathode, 2 Red_anode, 3 YellowGreen_anode, 4 RED_cathode

## LDFM33PVR
designator U?
pins: 1 OUT, 2 NC, 3 PG, 4 GND, 5 EN, 6 IN, 7 EP

## LDFMPVR
designator U?
pins: 1 OUT, 2 ADJ, 3 PG, 4 GND, 5 EN, 6 IN, 7 EP

## LDFPUR
designator U?
pins: 1 Vout, 2 ADJ, 3 PG, 4 GND, 5 EN, 6 Vin, EP GND

## LDK120M
designator U?
pins: 1 VIN (power), 2 GND, 3 EN, 4 BY, 5 VOUT (power)

## LDK120M33R
designator U?
pins: 1 VIN (power), 2 GND, 3 EN, 4 BYPASS, 5 VOUT (power)

## LDK120M-R
designator U?
pins: 1 VIN (power), 2 GND, 3 EN, 4 ADJ, 5 VOUT (power)

## LDK130M15R
designator U?
pins: 1 VIN (power), 2 GND, 3 EN, 4 BYPASS, 5 VOUT (power)

## LDK130PU12R
designator U?
pins: 1 VOUT, 2 GND, 3 BYP, 4 EN, 5 NC, 6 VIN

## LDK320M-R
designator U?
pins: 1 VIN (power), 2 GND, 3 EN, 4 ADJ, 5 VOUT (power)

## LDL112PV33R
designator U?
pins: 1 EN, 2 GND, 3 NC, 4 Vout, 5 NC, 6 Vin, EP

## LDLN025J18R
designator U?
pins: A1 Vin, A2 Vout, B1 EN, B2 GND

## LDO40L
designator U?
pins: 1 GND, 2 EN, 3 Vin, 4 Vout, 5 Vsense, 6 ADJ/NC, EP PAD

## LED_BICOLOR
designator LD?
pins: 1 Red_anode, 2 Green_cathode, 3 RED_cathode, 4 Green_anode

## LED_blue
designator LD?
pins: 1, 2

## LED_green
designator LD?
pins: 1, 2

## LED_Holder
designator HW?
pins: 1 A, 2 K

## LED_orange
designator LD?
pins: 1, 2

## LED_POWER_amber
designator LD?
pins: A1 A, A2 A, A3 A, A4 A, C1 C, C2 C

## LED_POWER_RGB
designator LD?
pins: 1 K3, 2 K2, 3 K1, 4 A1, 5 A2, 6 A3, 7 SLUG

## LED_red
designator LD?
pins: 1, 2

## LED_RGB
designator LD?
pins: 1 A1, 2 K2, 3 K3, 4 K4

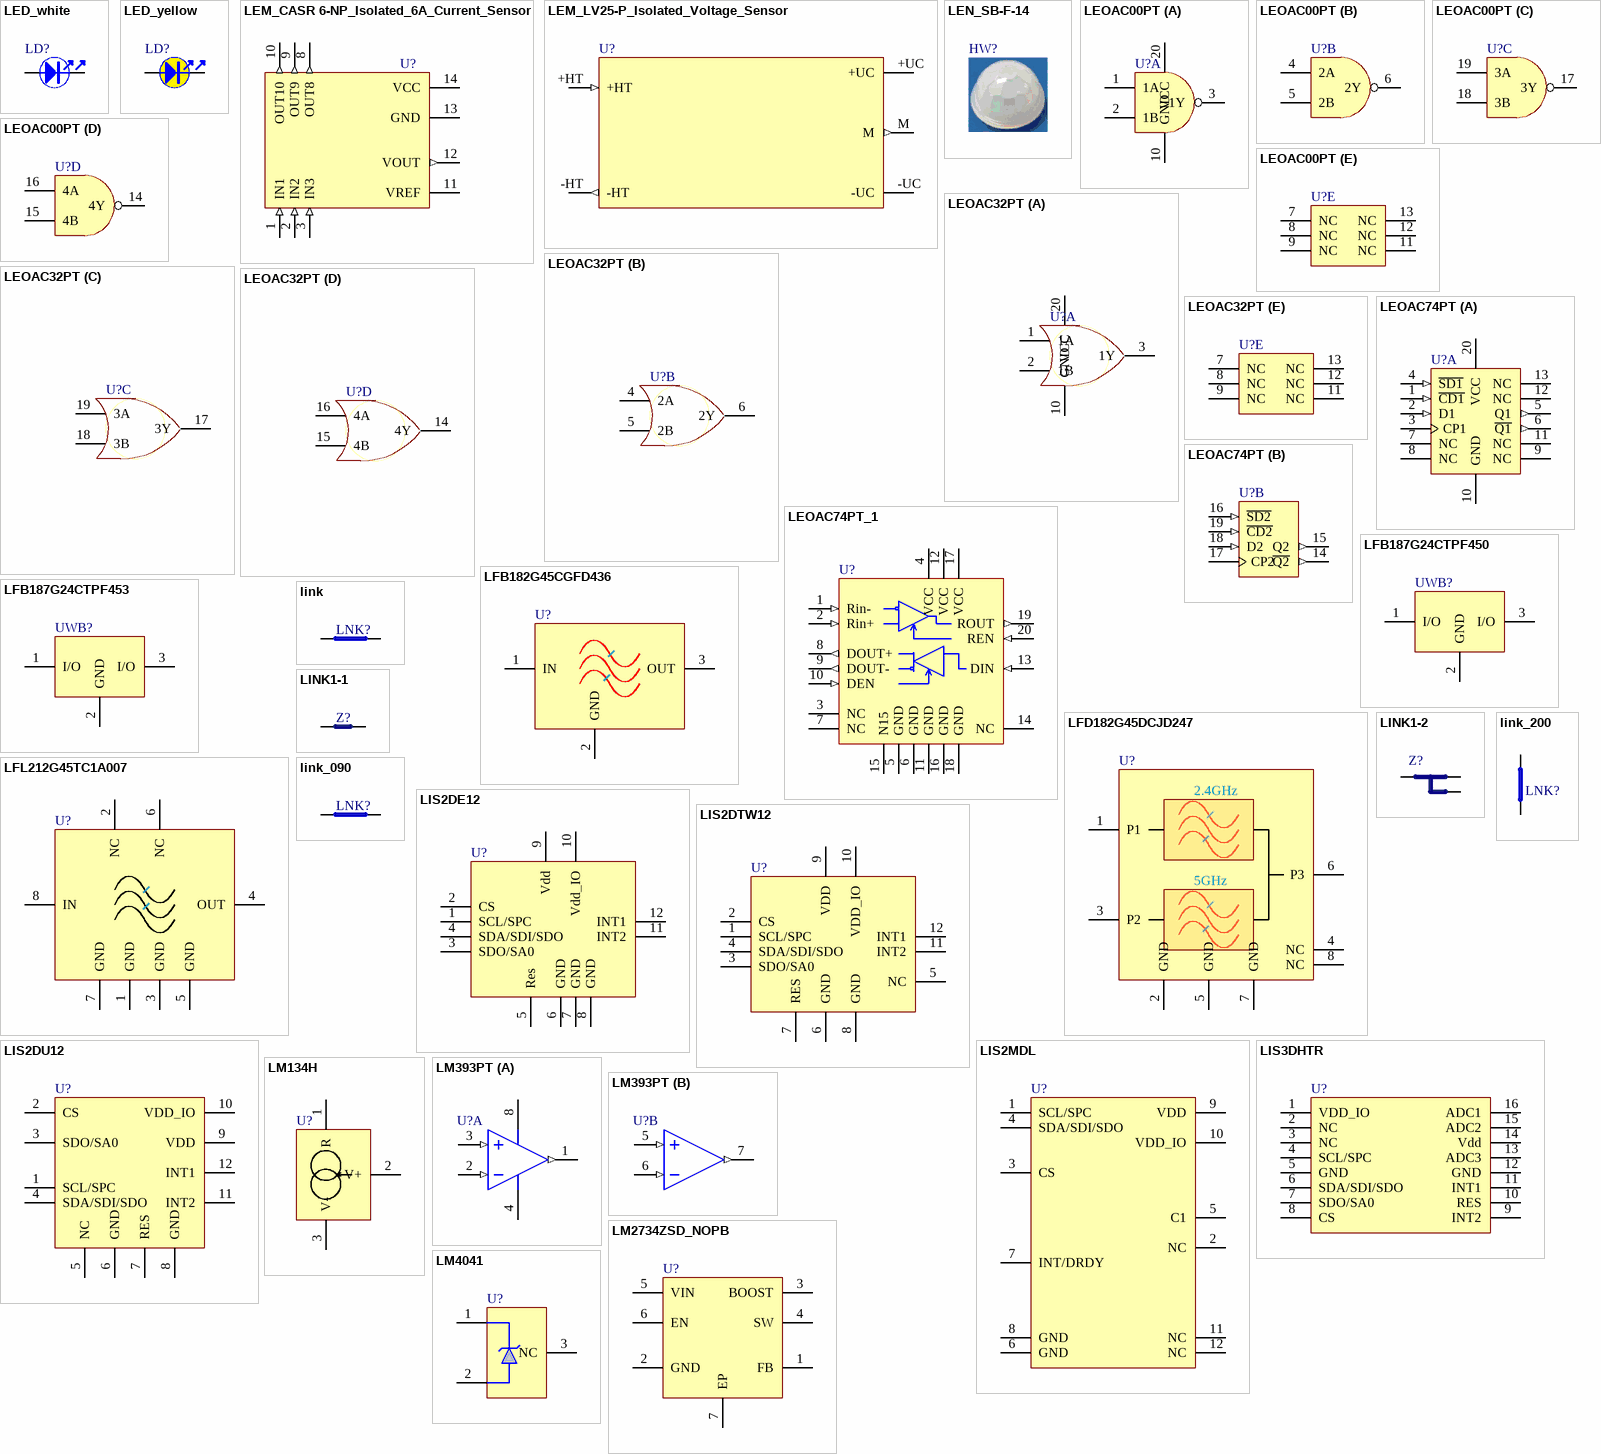
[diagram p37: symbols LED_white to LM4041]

## LED_white
designator LD?
pins: 1, 2

## LED_yellow
designator LD?
pins: 1, 2

## LEM_CASR 6-NP_Isolated_6A_Current_Sensor
designator U?
pins: 1 IN1 (in), 2 IN2 (in), 3 IN3 (in), 8 OUT8 (out), 9 OUT9 (out), 10 OUT10 (out), 11 VREF (power), 12 VOUT (out), 13 GND (power), 14 VCC (power)

## LEM_LV25-P_Isolated_Voltage_Sensor
designator U?
pins: +HT (in), +UC (power), -HT (out), -UC (power), M (out)

## LEN_SB-F-14
designator HW?

## LEOAC00PT
designator U?
part A pins: 1 NC hidden, 1 1A, 2 1B, 3 1Y, 10 GND, 20 VCC
part B pins: 4 2A, 5 2B, 6 2Y
part C pins: 17 3Y, 18 3B, 19 3A
part D pins: 14 4Y, 15 4B, 16 4A
part E pins: 7 NC, 8 NC, 9 NC, 11 NC, 12 NC, 13 NC

## LEOAC32PT
designator U?
part A pins: 1 NC hidden, 1 1A, 2 1B, 3 1Y, 10 GND, 20 VCC
part B pins: 4 2A, 5 2B, 6 2Y
part C pins: 17 3Y, 18 3B, 19 3A
part D pins: 14 4Y, 15 4B, 16 4A
part E pins: 7 NC, 8 NC, 9 NC, 11 NC, 12 NC, 13 NC

## LEOAC74PT
designator U?
part A pins: 1 ~{CD1} (in), 2 D1 (in), 3 CP1, 4 ~{SD1} (in), 5 Q1 (out), 6 ~{Q1} (out), 7 NC, 8 NC, 9 NC, 10 GND, 11 NC, 12 NC, 13 NC, 20 VCC (power)
part B pins: 14 ~{Q2} (out), 15 Q2 (out), 16 ~{SD2} (in), 17 CP2, 18 D2 (in), 19 ~{CD2} (in)

## LEOAC74PT_1
designator U?
pins: 1 Rin- (in), 2 Rin+ (in), 3 NC, 4 VCC (power), 5 GND, 6 GND, 7 NC, 8 DOUT+ (out), 9 DOUT- (out), 10 DEN (in), 11 GND, 12 VCC (power), 13 DIN (in), 14 NC, 15 N15, 16 GND, 17 VCC (power), 18 GND (power), 19 ROUT (out), 20 REN (in)

## LFB182G45CGFD436
designator U?
pins: 1 IN, 2 GND, 3 OUT

## LFB187G24CTPF450
designator UWB?
pins: 1 I/O, 2 GND (power), 3 I/O

## LFB187G24CTPF453
designator UWB?
pins: 1 I/O, 2 GND, 3 I/O

## LFD182G45DCJD247
designator U?
pins: 1 P1, 2 GND, 3 P2, 4 NC, 5 GND, 6 P3, 7 GND, 8 NC

## LFL212G45TC1A007
designator U?
pins: 1 GND, 2 NC, 3 GND, 4 OUT, 5 GND, 6 NC, 7 GND, 8 IN

## link
designator LNK?  (no BOM)
pins: 1, 2

## LINK1-1
designator Z?  (net tie, no BOM)
pins: 1, 2

## LINK1-2
designator Z?  (net tie, no BOM)
pins: 1, 2, 3

## link_090
designator LNK?  (no BOM)
footprint LINK200
pins: 1, 2

## link_200
designator LNK?  (no BOM)
pins: 1, 2

## LIS2DE12
designator U?
pins: 1 SCL/SPC, 2 CS, 3 SDO/SA0, 4 SDA/SDI/SDO, 5 Res, 6 GND, 7 GND, 8 GND, 9 Vdd, 10 Vdd_IO, 11 INT2, 12 INT1

## LIS2DTW12
designator U?
pins: 1 SCL/SPC, 2 CS, 3 SDO/SA0, 4 SDA/SDI/SDO, 5 NC, 6 GND, 7 RES, 8 GND, 9 VDD, 10 VDD_IO, 11 INT2, 12 INT1

## LIS2DU12
designator U?
pins: 1 SCL/SPC, 2 CS, 3 SDO/SA0, 4 SDA/SDI/SDO, 5 NC, 6 GND, 7 RES, 8 GND, 9 VDD, 10 VDD_IO, 11 INT2, 12 INT1

## LIS2MDL
designator U?
pins: 1 SCL/SPC, 2 NC, 3 CS, 4 SDA/SDI/SDO, 5 C1, 6 GND, 7 INT/DRDY, 8 GND, 9 VDD, 10 VDD_IO, 11 NC, 12 NC

## LIS3DHTR
designator U?
pins: 1 VDD_IO, 2 NC, 3 NC, 4 SCL/SPC, 5 GND, 6 SDA/SDI/SDO, 7 SDO/SA0, 8 CS, 9 INT2, 10 RES, 11 INT1, 12 GND, 13 ADC3, 14 Vdd, 15 ADC2, 16 ADC1

## LM134H
designator U?
pins: 1 R, 2 V+, 3 V-

## LM393PT
designator U?
part A pins: 1 OUT (out), 2 IN- (in), 3 IN+ (in), 4 V- (power), 8 V+ (power)
part B pins: 5 IN+ (in), 6 IN- (in), 7 OUT (out)

## LM2734ZSD_NOPB
designator U?
pins: 1 FB, 2 GND, 3 BOOST, 4 SW, 5 VIN, 6 EN, 7 EP

## LM4041
designator U?
pins: 1, 2, 3 NC

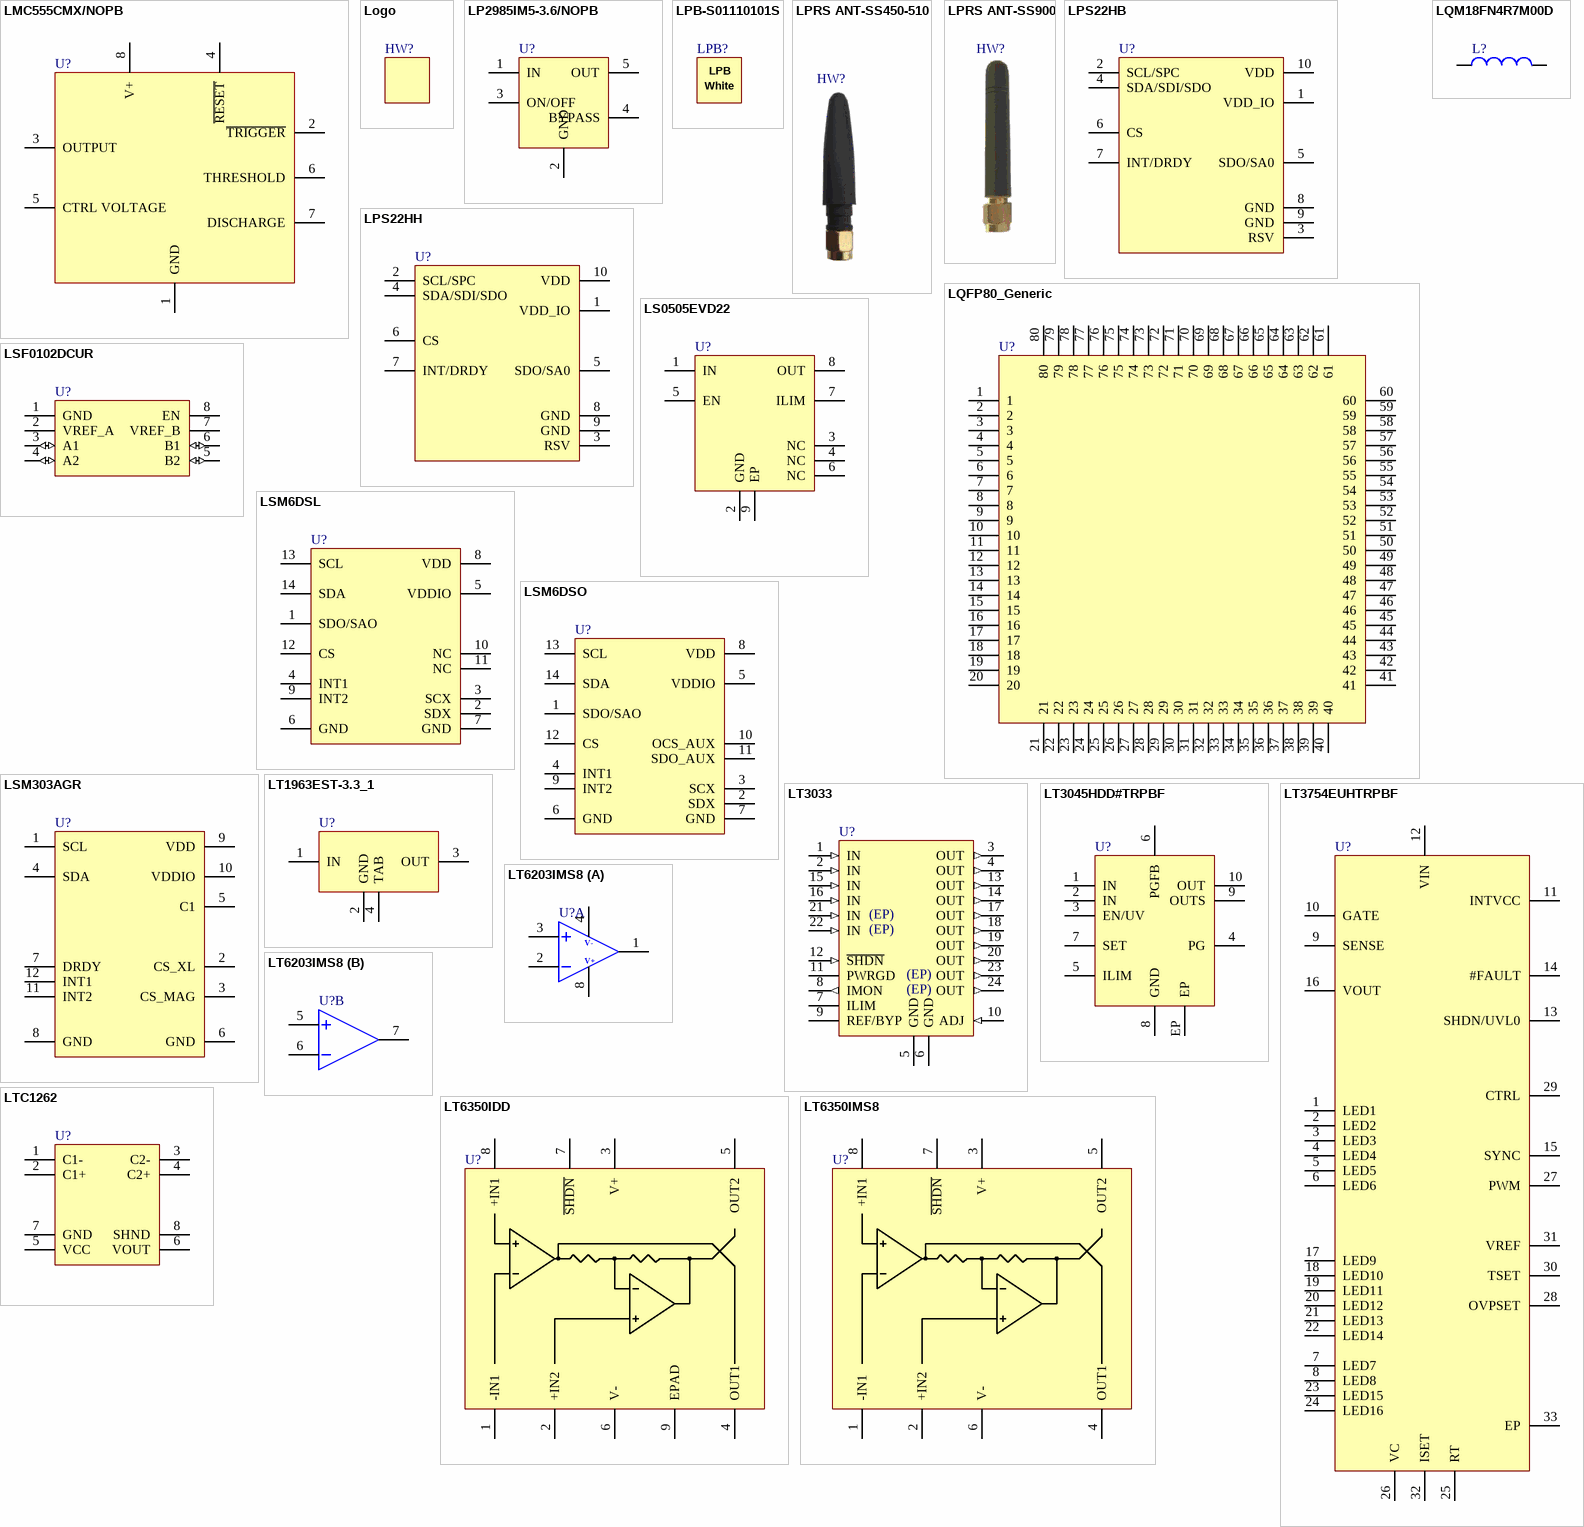
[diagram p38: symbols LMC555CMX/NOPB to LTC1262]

## LMC555CMX/NOPB
designator U?
pins: 1 GND, 2 ~{TRIGGER}, 3 OUTPUT, 4 ~{RESET}, 5 CTRL VOLTAGE, 6 THRESHOLD, 7 DISCHARGE, 8 V+

## Logo
designator HW?  (no BOM)

## LP2985IM5-3.6/NOPB
designator U?
pins: 1 IN, 2 GND, 3 ON/OFF, 4 BYPASS, 5 OUT

## LPB-S01110101S
designator LPB?

## LPRS ANT-SS450-510
designator HW?

## LPRS ANT-SS900
designator HW?

## LPS22HB
designator U?
pins: 1 VDD_IO, 2 SCL/SPC, 3 RSV, 4 SDA/SDI/SDO, 5 SDO/SA0, 6 CS, 7 INT/DRDY, 8 GND, 9 GND, 10 VDD

## LPS22HH
designator U?
pins: 1 VDD_IO, 2 SCL/SPC, 3 RSV, 4 SDA/SDI/SDO, 5 SDO/SA0, 6 CS, 7 INT/DRDY, 8 GND, 9 GND, 10 VDD

## LQFP80_Generic
designator U?
pins: 1, 2, 3, 4, 5, 6, 7, 8, 9, 10, 11, 12, 13, 14, 15, 16, 17, 18, 19, 20, 21, 22, 23, 24, 25, 26, 27, 28, 29, 30, 31, 32, 33, 34, 35, 36, 37, 38, 39, 40, 41, 42, 43, 44, 45, 46, 47, 48, 49, 50, 51, 52, 53, 54, 55, 56, 57, 58, 59, 60, 61, 62, 63, 64, 65, 66, 67, 68, 69, 70, 71, 72, 73, 74, 75, 76, 77, 78, 79, 80

## LQM18FN4R7M00D
designator L?
pins: 1, 2

## LS0505EVD22
designator U?
pins: 1 IN, 2 GND, 3 NC, 4 NC, 5 EN, 6 NC, 7 ILIM, 8 OUT, 9 EP

## LSF0102DCUR
designator U?
pins: 1 GND "Transmit Data Input", 2 VREF_A (power) "Low voltage reference", 3 A1 (io), 4 A2 (io), 5 B2 (io) "High voltage", 6 B1 (io) "High voltage", 7 VREF_B (power) "High votage polarisation through 200K", 8 EN (power) "High votage polarisation through 200K"

## LSM6DSL
designator U?
pins: 1 SDO/SAO, 2 SDX, 3 SCX, 4 INT1, 5 VDDIO, 6 GND, 7 GND, 8 VDD, 9 INT2, 10 NC, 11 NC, 12 CS, 13 SCL, 14 SDA

## LSM6DSO
designator U?
pins: 1 SDO/SAO, 2 SDX, 3 SCX, 4 INT1, 5 VDDIO, 6 GND, 7 GND, 8 VDD, 9 INT2, 10 OCS_AUX, 11 SDO_AUX, 12 CS, 13 SCL, 14 SDA

## LSM303AGR
designator U?
pins: 1 SCL, 2 CS_XL, 3 CS_MAG, 4 SDA, 5 C1, 6 GND, 7 DRDY, 8 GND, 9 VDD, 10 VDDIO, 11 INT2, 12 INT1

## LT1963EST-3.3_1
designator U?
pins: 1 IN, 2 GND, 3 OUT, 4 TAB

## LT3033
designator U?
pins: 1 IN (in), 2 IN (in), 3 OUT (out), 4 OUT (out), 5 GND, 6 GND, 7 ILIM, 8 IMON (out), 9 REF/BYP, 10 ADJ (in), 11 PWRGD (oc), 12 ~{SHDN} (in), 13 OUT (out), 14 OUT (out), 15 IN (in), 16 IN (in), 17 OUT (out), 18 OUT (out), 19 OUT (out), 20 OUT (out), 21 IN (in), 22 IN (in), 23 OUT (out), 24 OUT (out)

## LT3045HDD#TRPBF
designator U?
pins: 1 IN, 2 IN, 3 EN/UV, 4 PG, 5 ILIM, 6 PGFB, 7 SET, 8 GND, 9 OUTS, 10 OUT, EP

## LT3754EUHTRPBF
designator U?
pins: 1 LED1, 2 LED2, 3 LED3, 4 LED4, 5 LED5, 6 LED6, 7 LED7, 8 LED8, 9 SENSE, 10 GATE, 11 INTVCC, 12 VIN, 13 SHDN/UVL0, 14 #FAULT, 15 SYNC, 16 VOUT, 17 LED9, 18 LED10, 19 LED11, 20 LED12, 21 LED13, 22 LED14, 23 LED15, 24 LED16, 25 RT, 26 VC, 27 PWM, 28 OVPSET, 29 CTRL, 30 TSET, 31 VREF, 32 ISET, 33 EP

## LT6203IMS8
designator U?
part A pins: 1, 2, 3, 4, 8
part B pins: 5, 6, 7

## LT6350IDD
designator U?
pins: 1 -IN1, 2 +IN2, 3 V+, 4 OUT1, 5 OUT2, 6 V-, 7 ~{SHDN}, 8 +IN1, 9 EPAD

## LT6350IMS8
designator U?
pins: 1 -IN1, 2 +IN2, 3 V+, 4 OUT1, 5 OUT2, 6 V-, 7 ~{SHDN}, 8 +IN1

## LTC1262
designator U?
pins: 1 C1-, 2 C1+, 3 C2-, 4 C2+, 5 VCC, 6 VOUT, 7 GND, 8 SHND

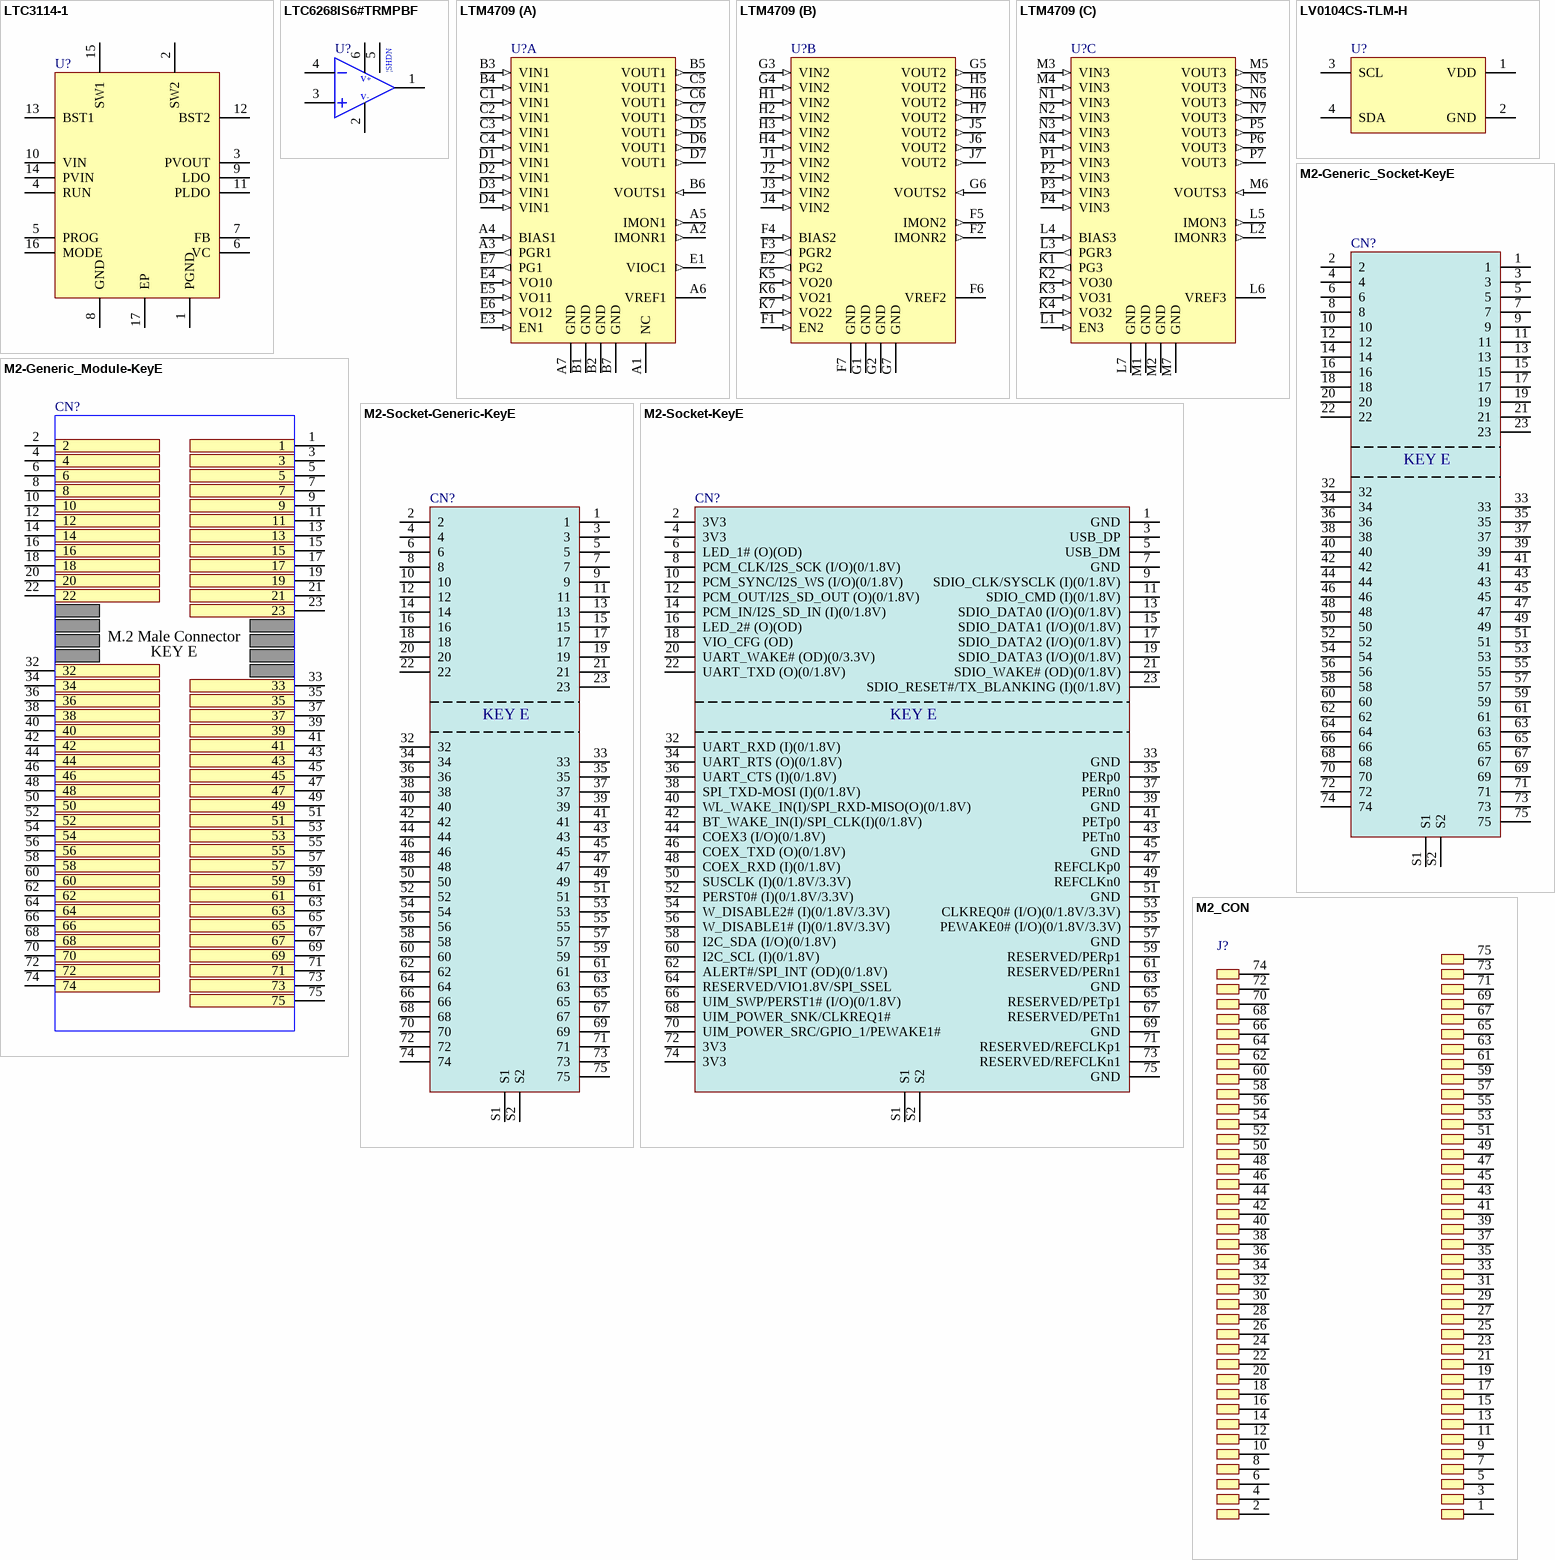
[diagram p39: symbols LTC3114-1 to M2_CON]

## LTC3114-1
designator U?
pins: 1 PGND, 2 SW2, 3 PVOUT, 4 RUN, 5 PROG, 6 VC, 7 FB, 8 GND, 9 LDO, 10 VIN, 11 PLDO, 12 BST2, 13 BST1, 14 PVIN, 15 SW1, 16 MODE, 17 EP

## LTC6268IS6#TRMPBF
designator U?
pins: 1 OUT, 2 V-, 3 IN+, 4 IN-, 5 ~{SHDN}, 6 V+

## LTM4709
designator U?
part A pins: A1 NC, A2 IMONR1 (out), A3 PGR1 (out), A4 BIAS1 (in), A5 IMON1 (out), A6 VREF1, A7 GND, B1 GND, B2 GND, B3 VIN1 (in), B4 VIN1 (in), B5 VOUT1 (out), B6 VOUTS1 (in), B7 GND, C1 VIN1 (in), C2 VIN1 (in), C3 VIN1 (in), C4 VIN1 (in), C5 VOUT1 (out), C6 VOUT1 (out), C7 VOUT1 (out), D1 VIN1 (in), D2 VIN1 (in), D3 VIN1 (in), D4 VIN1 (in), D5 VOUT1 (out), D6 VOUT1 (out), D7 VOUT1 (out), E1 VIOC1 (out), E3 EN1 (in), E4 VO10 (in), E5 VO11 (in), E6 VO12 (in), E7 PG1 (out)
part B pins: E2 PG2 (out), F1 EN2 (in), F2 IMONR2 (out), F3 PGR2 (out), F4 BIAS2 (in), F5 IMON2 (out), F6 VREF2, F7 GND, G1 GND, G2 GND, G3 VIN2 (in), G4 VIN2 (in), G5 VOUT2 (out), G6 VOUTS2 (in), G7 GND, H1 VIN2 (in), H2 VIN2 (in), H3 VIN2 (in), H4 VIN2 (in), H5 VOUT2 (out), H6 VOUT2 (out), H7 VOUT2 (out), J1 VIN2 (in), J2 VIN2 (in), J3 VIN2 (in), J4 VIN2 (in), J5 VOUT2 (out), J6 VOUT2 (out), J7 VOUT2 (out), K5 VO20 (in), K6 VO21 (in), K7 VO22 (in)
part C pins: K1 PG3 (out), K2 VO30 (in), K3 VO31 (in), K4 VO32 (in), L1 EN3 (in), L2 IMONR3 (out), L3 PGR3 (out), L4 BIAS3 (in), L5 IMON3 (out), L6 VREF3, L7 GND, M1 GND, M2 GND, M3 VIN3 (in), M4 VIN3 (in), M5 VOUT3 (out), M6 VOUTS3 (in), M7 GND, N1 VIN3 (in), N2 VIN3 (in), N3 VIN3 (in), N4 VIN3 (in), N5 VOUT3 (out), N6 VOUT3 (out), N7 VOUT3 (out), P1 VIN3 (in), P2 VIN3 (in), P3 VIN3 (in), P4 VIN3 (in), P5 VOUT3 (out), P6 VOUT3 (out), P7 VOUT3 (out)

## LV0104CS-TLM-H
designator U?
pins: 1 VDD, 2 GND, 3 SCL, 4 SDA

## M2-Generic_Module-KeyE
designator CN?
Alternate mode is available; Normal Symbol mode: generic M2 card symbol; Alternate1 Symbol mode: Specific M2 card symbol
pins: 1, 2, 3, 4, 5, 6, 7, 8, 9, 10, 11, 12, 13, 14, 15, 16, 17, 18, 19, 20, 21, 22, 23, 32, 33, 34, 35, 36, 37, 38, 39, 40, 41, 42, 43, 44, 45, 46, 47, 48, 49, 50, 51, 52, 53, 54, 55, 56, 57, 58, 59, 60, 61, 62, 63, 64, 65, 66, 67, 68, 69, 70, 71, 72, 73, 74, 75
1 alternate drawing of the same symbol

## M2-Generic_Socket-KeyE
designator CN?
Alternate mode is available; Alternate1 Symbol mode: specific M2 connector symbol; Normal Symbol mode: generic M2 connector symbol
pins: 1, 2, 3, 4, 5, 6, 7, 8, 9, 10, 11, 12, 13, 14, 15, 16, 17, 18, 19, 20, 21, 22, 23, 32, 33, 34, 35, 36, 37, 38, 39, 40, 41, 42, 43, 44, 45, 46, 47, 48, 49, 50, 51, 52, 53, 54, 55, 56, 57, 58, 59, 60, 61, 62, 63, 64, 65, 66, 67, 68, 69, 70, 71, 72, 73, 74, 75, S1, S2
1 alternate drawing of the same symbol

## M2-Socket-Generic-KeyE
designator CN?
pins: 1, 2, 3, 4, 5, 6, 7, 8, 9, 10, 11, 12, 13, 14, 15, 16, 17, 18, 19, 20, 21, 22, 23, 32, 33, 34, 35, 36, 37, 38, 39, 40, 41, 42, 43, 44, 45, 46, 47, 48, 49, 50, 51, 52, 53, 54, 55, 56, 57, 58, 59, 60, 61, 62, 63, 64, 65, 66, 67, 68, 69, 70, 71, 72, 73, 74, 75, S1, S2

## M2-Socket-KeyE
designator CN?
pins: 1 GND, 2 3V3, 3 USB_DP, 4 3V3, 5 USB_DM, 6 LED_1# (O)(OD), 7 GND, 8 PCM_CLK/I2S_SCK (I/O)(0/1.8V), 9 SDIO_CLK/SYSCLK (I)(0/1.8V), 10 PCM_SYNC/I2S_WS (I/O)(0/1.8V), 11 SDIO_CMD (I)(0/1.8V), 12 PCM_OUT/I2S_SD_OUT (O)(0/1.8V), 13 SDIO_DATA0 (I/O)(0/1.8V), 14 PCM_IN/I2S_SD_IN (I)(0/1.8V), 15 SDIO_DATA1 (I/O)(0/1.8V), 16 LED_2# (O)(OD), 17 SDIO_DATA2 (I/O)(0/1.8V), 18 VIO_CFG (OD), 19 SDIO_DATA3 (I/O)(0/1.8V), 20 UART_WAKE# (OD)(0/3.3V), 21 SDIO_WAKE# (OD)(0/1.8V), 22 UART_TXD (O)(0/1.8V), 23 SDIO_RESET#/TX_BLANKING (I)(0/1.8V), 32 UART_RXD (I)(0/1.8V), 33 GND, 34 UART_RTS (O)(0/1.8V), 35 PERp0, 36 UART_CTS (I)(0/1.8V), 37 PERn0, 38 SPI_TXD-MOSI (I)(0/1.8V), 39 GND, 40 WL_WAKE_IN(I)/SPI_RXD-MISO(O)(0/1.8V), 41 PETp0, 42 BT_WAKE_IN(I)/SPI_CLK(I)(0/1.8V), 43 PETn0, 44 COEX3 (I/O)(0/1.8V), 45 GND, 46 COEX_TXD (O)(0/1.8V), 47 REFCLKp0, 48 COEX_RXD (I)(0/1.8V), 49 REFCLKn0, 50 SUSCLK (I)(0/1.8V/3.3V), 51 GND, 52 PERST0# (I)(0/1.8V/3.3V), 53 CLKREQ0# (I/O)(0/1.8V/3.3V), 54 W_DISABLE2# (I)(0/1.8V/3.3V), 55 PEWAKE0# (I/O)(0/1.8V/3.3V), 56 W_DISABLE1# (I)(0/1.8V/3.3V), 57 GND, 58 I2C_SDA (I/O)(0/1.8V), 59 RESERVED/PERp1, 60 I2C_SCL (I)(0/1.8V), 61 RESERVED/PERn1, 62 ALERT#/SPI_INT (OD)(0/1.8V), 63 GND, 64 RESERVED/VIO1.8V/SPI_SSEL, 65 RESERVED/PETp1, 66 UIM_SWP/PERST1# (I/O)(0/1.8V), 67 RESERVED/PETn1, 68 UIM_POWER_SNK/CLKREQ1#, 69 GND, 70 UIM_POWER_SRC/GPIO_1/PEWAKE1#, 71 RESERVED/REFCLKp1, 72 3V3, 73 RESERVED/REFCLKn1, 74 3V3, 75 GND, S1, S2
1 alternate drawing of the same symbol

## M2_CON
designator J?
pins: 1, 2, 3, 4, 5, 6, 7, 8, 9, 10, 11, 12, 13, 14, 15, 16, 17, 18, 19, 20, 21, 22, 23, 24, 25, 26, 27, 28, 29, 30, 31, 32, 33, 34, 35, 36, 37, 38, 39, 40, 41, 42, 43, 44, 45, 46, 47, 48, 49, 50, 51, 52, 53, 54, 55, 56, 57, 58, 59, 60, 61, 62, 63, 64, 65, 66, 67, 68, 69, 70, 71, 72, 73, 74, 75

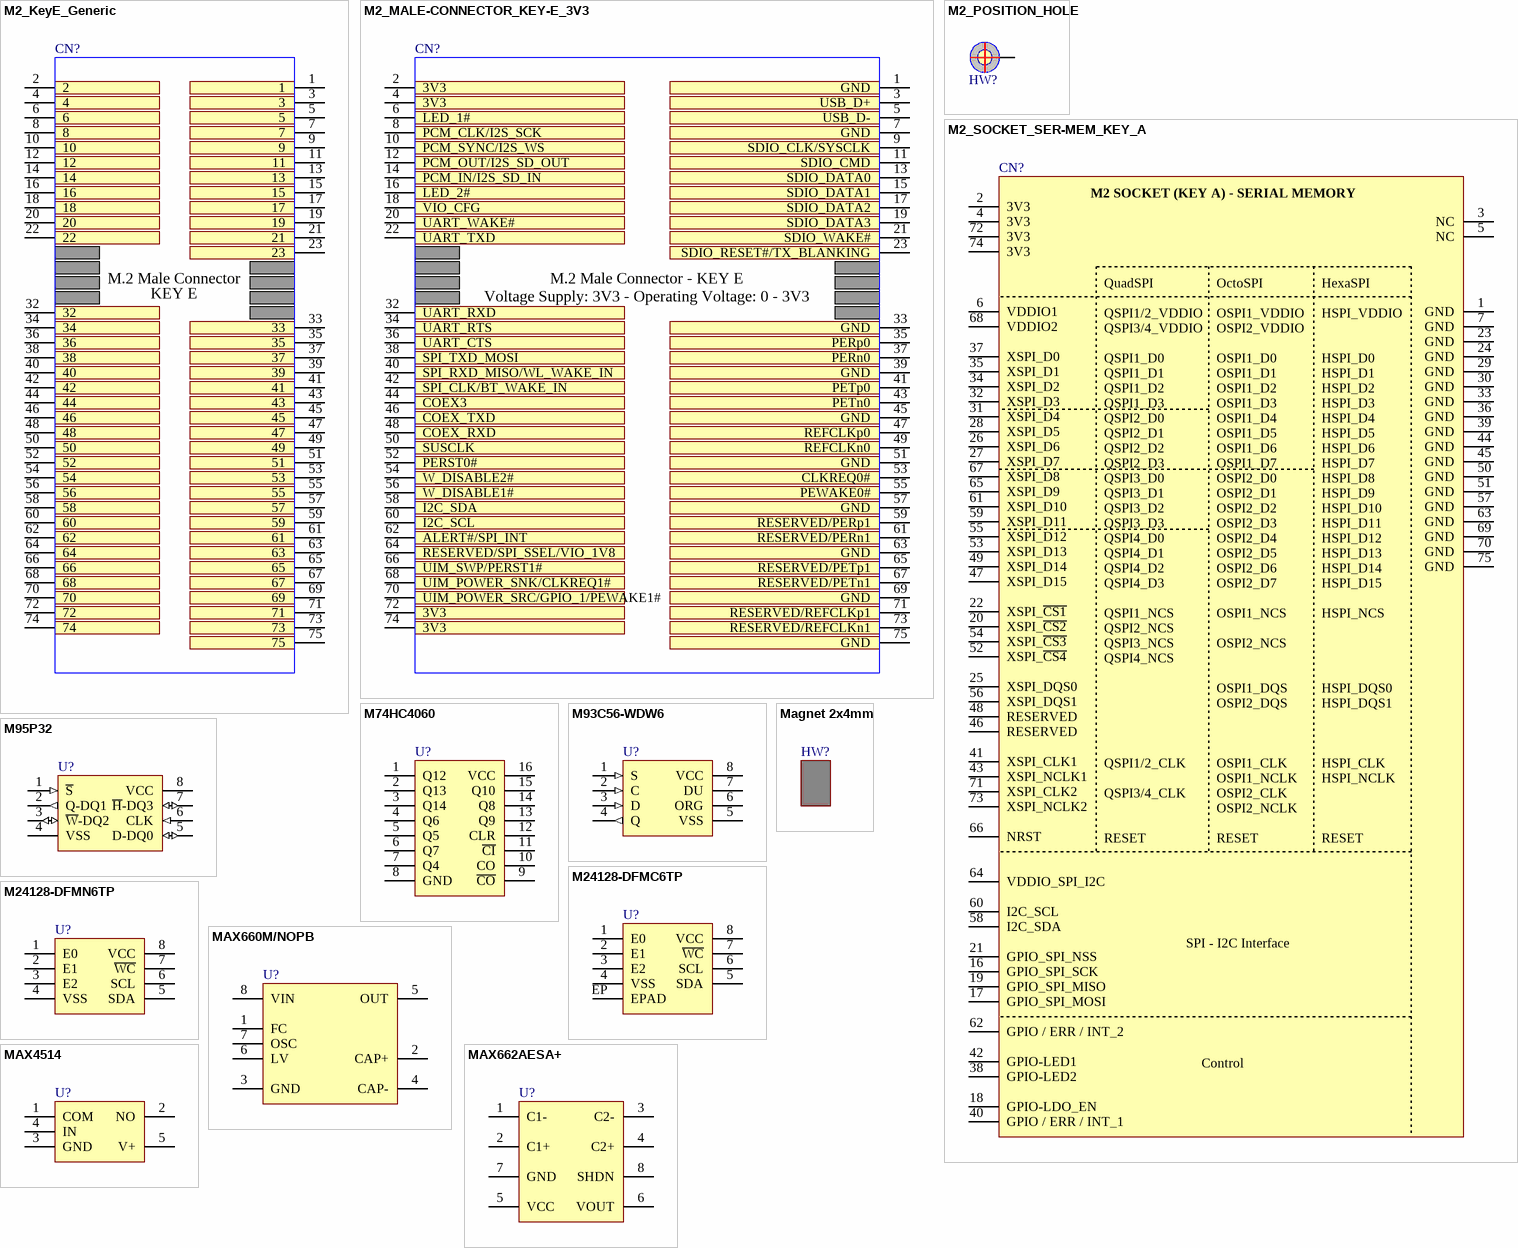
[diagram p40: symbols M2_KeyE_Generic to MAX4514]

## M2_KeyE_Generic
designator CN?
pins: 1, 2, 3, 4, 5, 6, 7, 8, 9, 10, 11, 12, 13, 14, 15, 16, 17, 18, 19, 20, 21, 22, 23, 32, 33, 34, 35, 36, 37, 38, 39, 40, 41, 42, 43, 44, 45, 46, 47, 48, 49, 50, 51, 52, 53, 54, 55, 56, 57, 58, 59, 60, 61, 62, 63, 64, 65, 66, 67, 68, 69, 70, 71, 72, 73, 74, 75

## M2_MALE-CONNECTOR_KEY-E_3V3
designator CN?  (no BOM)
pins: 1 GND, 2 3V3, 3 USB_D+, 4 3V3, 5 USB_D-, 6 LED_1#, 7 GND, 8 PCM_CLK/I2S_SCK, 9 SDIO_CLK/SYSCLK, 10 PCM_SYNC/I2S_WS, 11 SDIO_CMD, 12 PCM_OUT/I2S_SD_OUT, 13 SDIO_DATA0, 14 PCM_IN/I2S_SD_IN, 15 SDIO_DATA1, 16 LED_2#, 17 SDIO_DATA2, 18 VIO_CFG, 19 SDIO_DATA3, 20 UART_WAKE#, 21 SDIO_WAKE#, 22 UART_TXD, 23 SDIO_RESET#/TX_BLANKING, 32 UART_RXD, 33 GND, 34 UART_RTS, 35 PERp0, 36 UART_CTS, 37 PERn0, 38 SPI_TXD_MOSI, 39 GND, 40 SPI_RXD_MISO/WL_WAKE_IN, 41 PETp0, 42 SPI_CLK/BT_WAKE_IN, 43 PETn0, 44 COEX3, 45 GND, 46 COEX_TXD, 47 REFCLKp0, 48 COEX_RXD, 49 REFCLKn0, 50 SUSCLK, 51 GND, 52 PERST0#, 53 CLKREQ0#, 54 W_DISABLE2#, 55 PEWAKE0#, 56 W_DISABLE1#, 57 GND, 58 I2C_SDA, 59 RESERVED/PERp1, 60 I2C_SCL, 61 RESERVED/PERn1, 62 ALERT#/SPI_INT, 63 GND, 64 RESERVED/SPI_SSEL/VIO_1V8, 65 RESERVED/PETp1, 66 UIM_SWP/PERST1#, 67 RESERVED/PETn1, 68 UIM_POWER_SNK/CLKREQ1#, 69 GND, 70 UIM_POWER_SRC/GPIO_1/PEWAKE1#, 71 RESERVED/REFCLKp1, 72 3V3, 73 RESERVED/REFCLKn1, 74 3V3, 75 GND

## M2_POSITION_HOLE
designator HW?
pins: 1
